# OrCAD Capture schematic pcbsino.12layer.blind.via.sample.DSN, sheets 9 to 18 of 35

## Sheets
9 Pg10: DDR3 VTT: size C
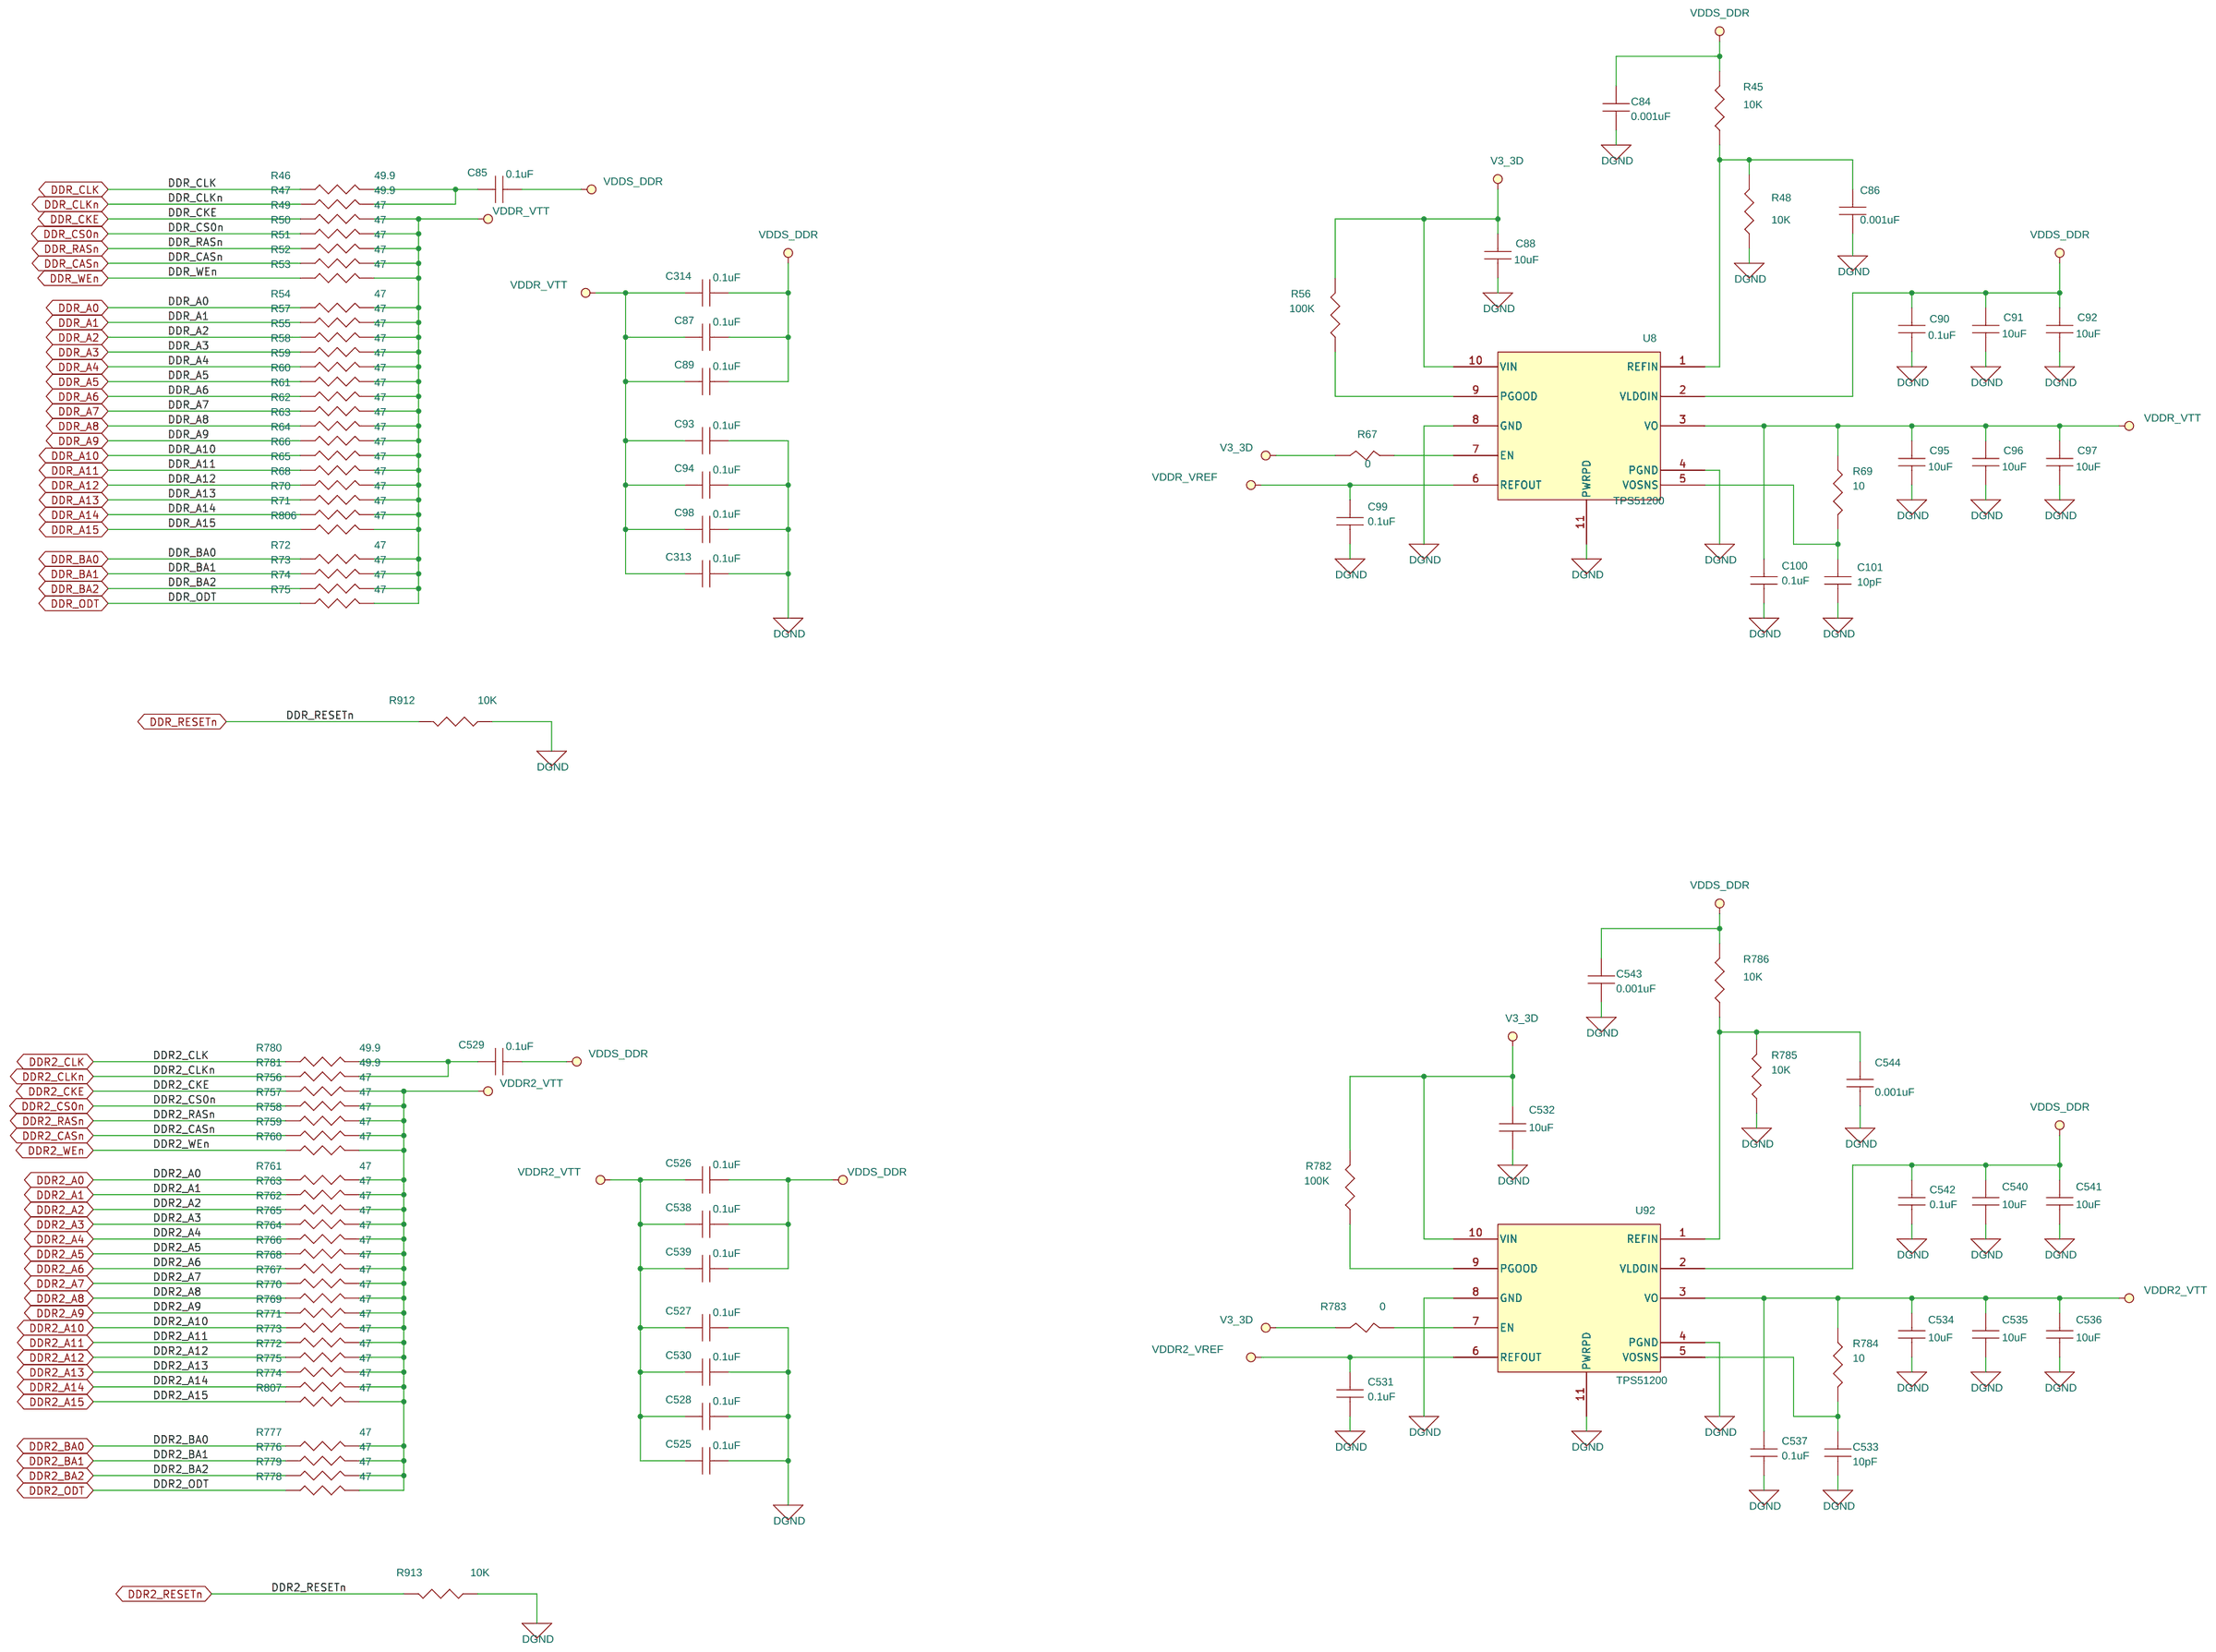
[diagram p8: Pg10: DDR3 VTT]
10 Pg01: Title Page
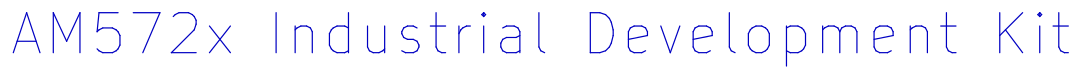
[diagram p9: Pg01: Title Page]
11 Pg34: IDK Mods: size B
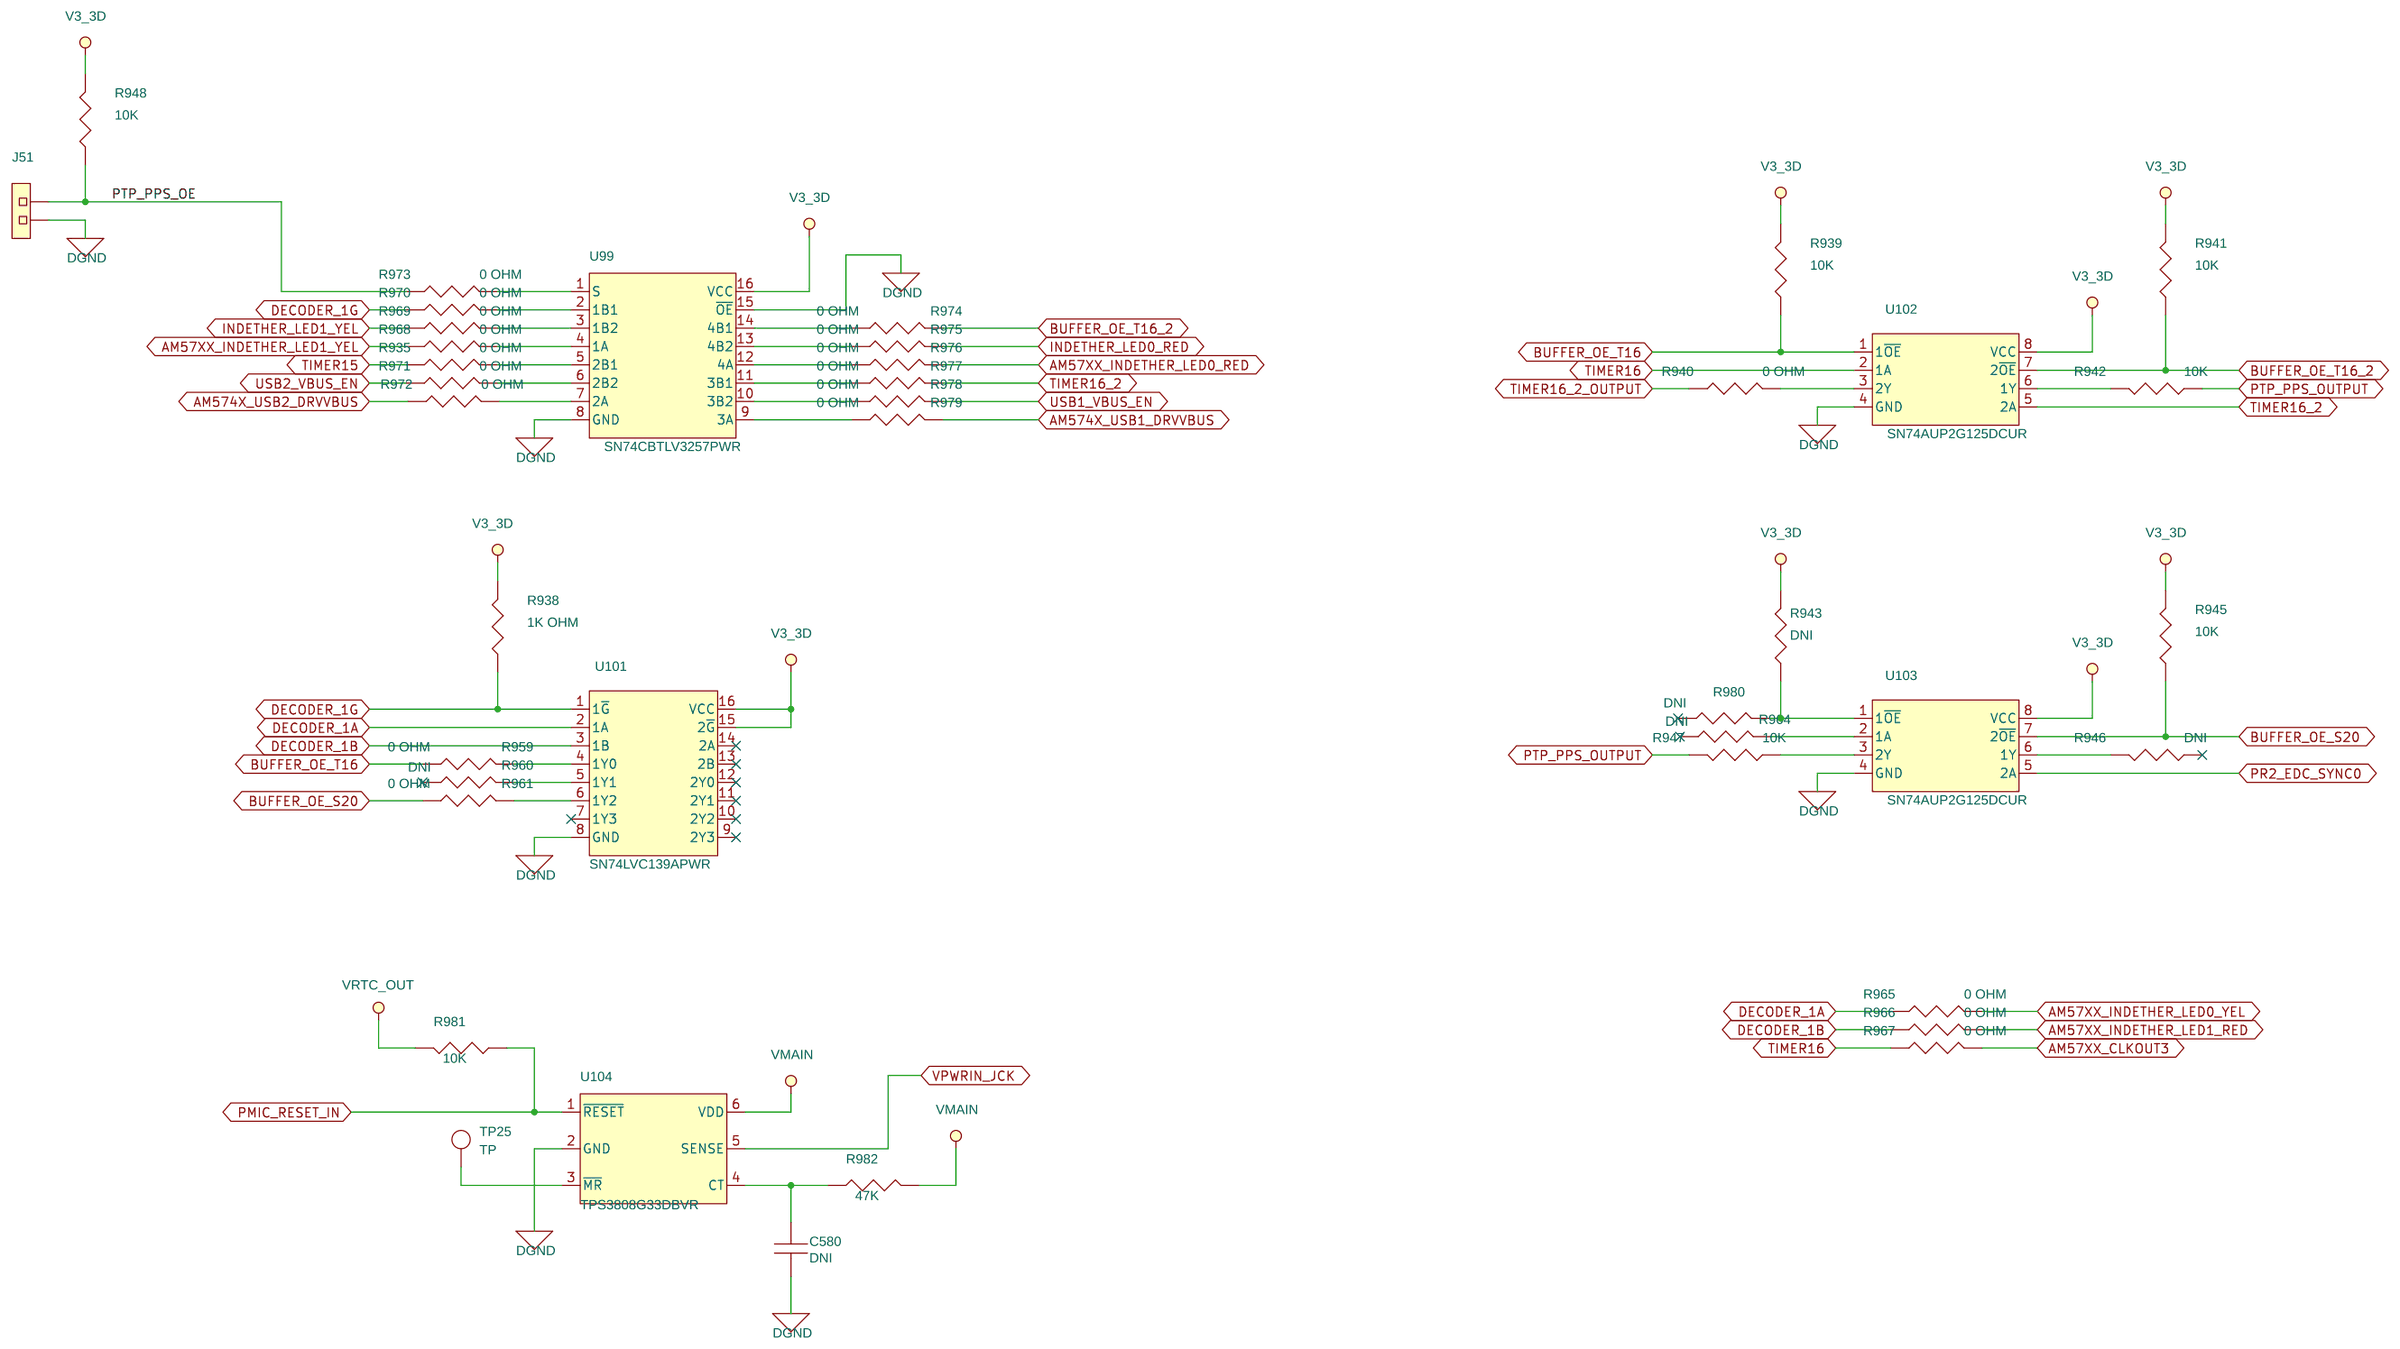
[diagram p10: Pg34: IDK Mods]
12 Pg29: Profibus: size C
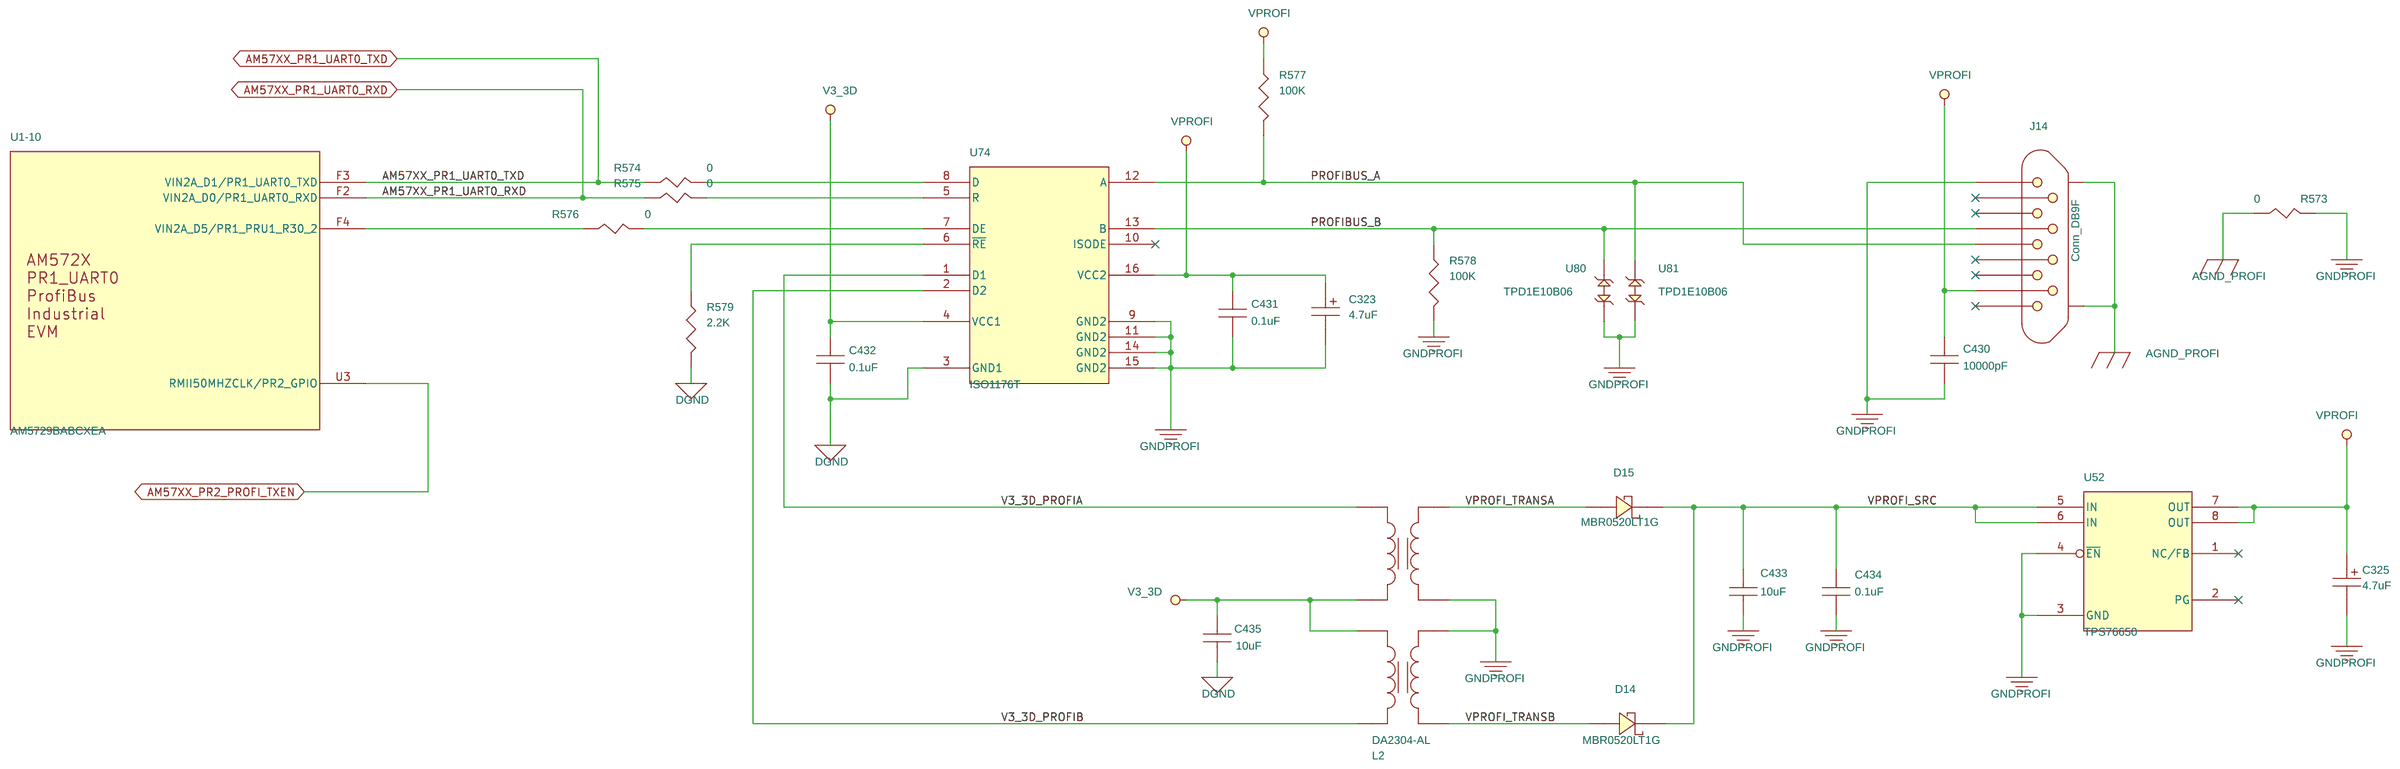
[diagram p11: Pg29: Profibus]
13 Pg16: Camera #1: size C
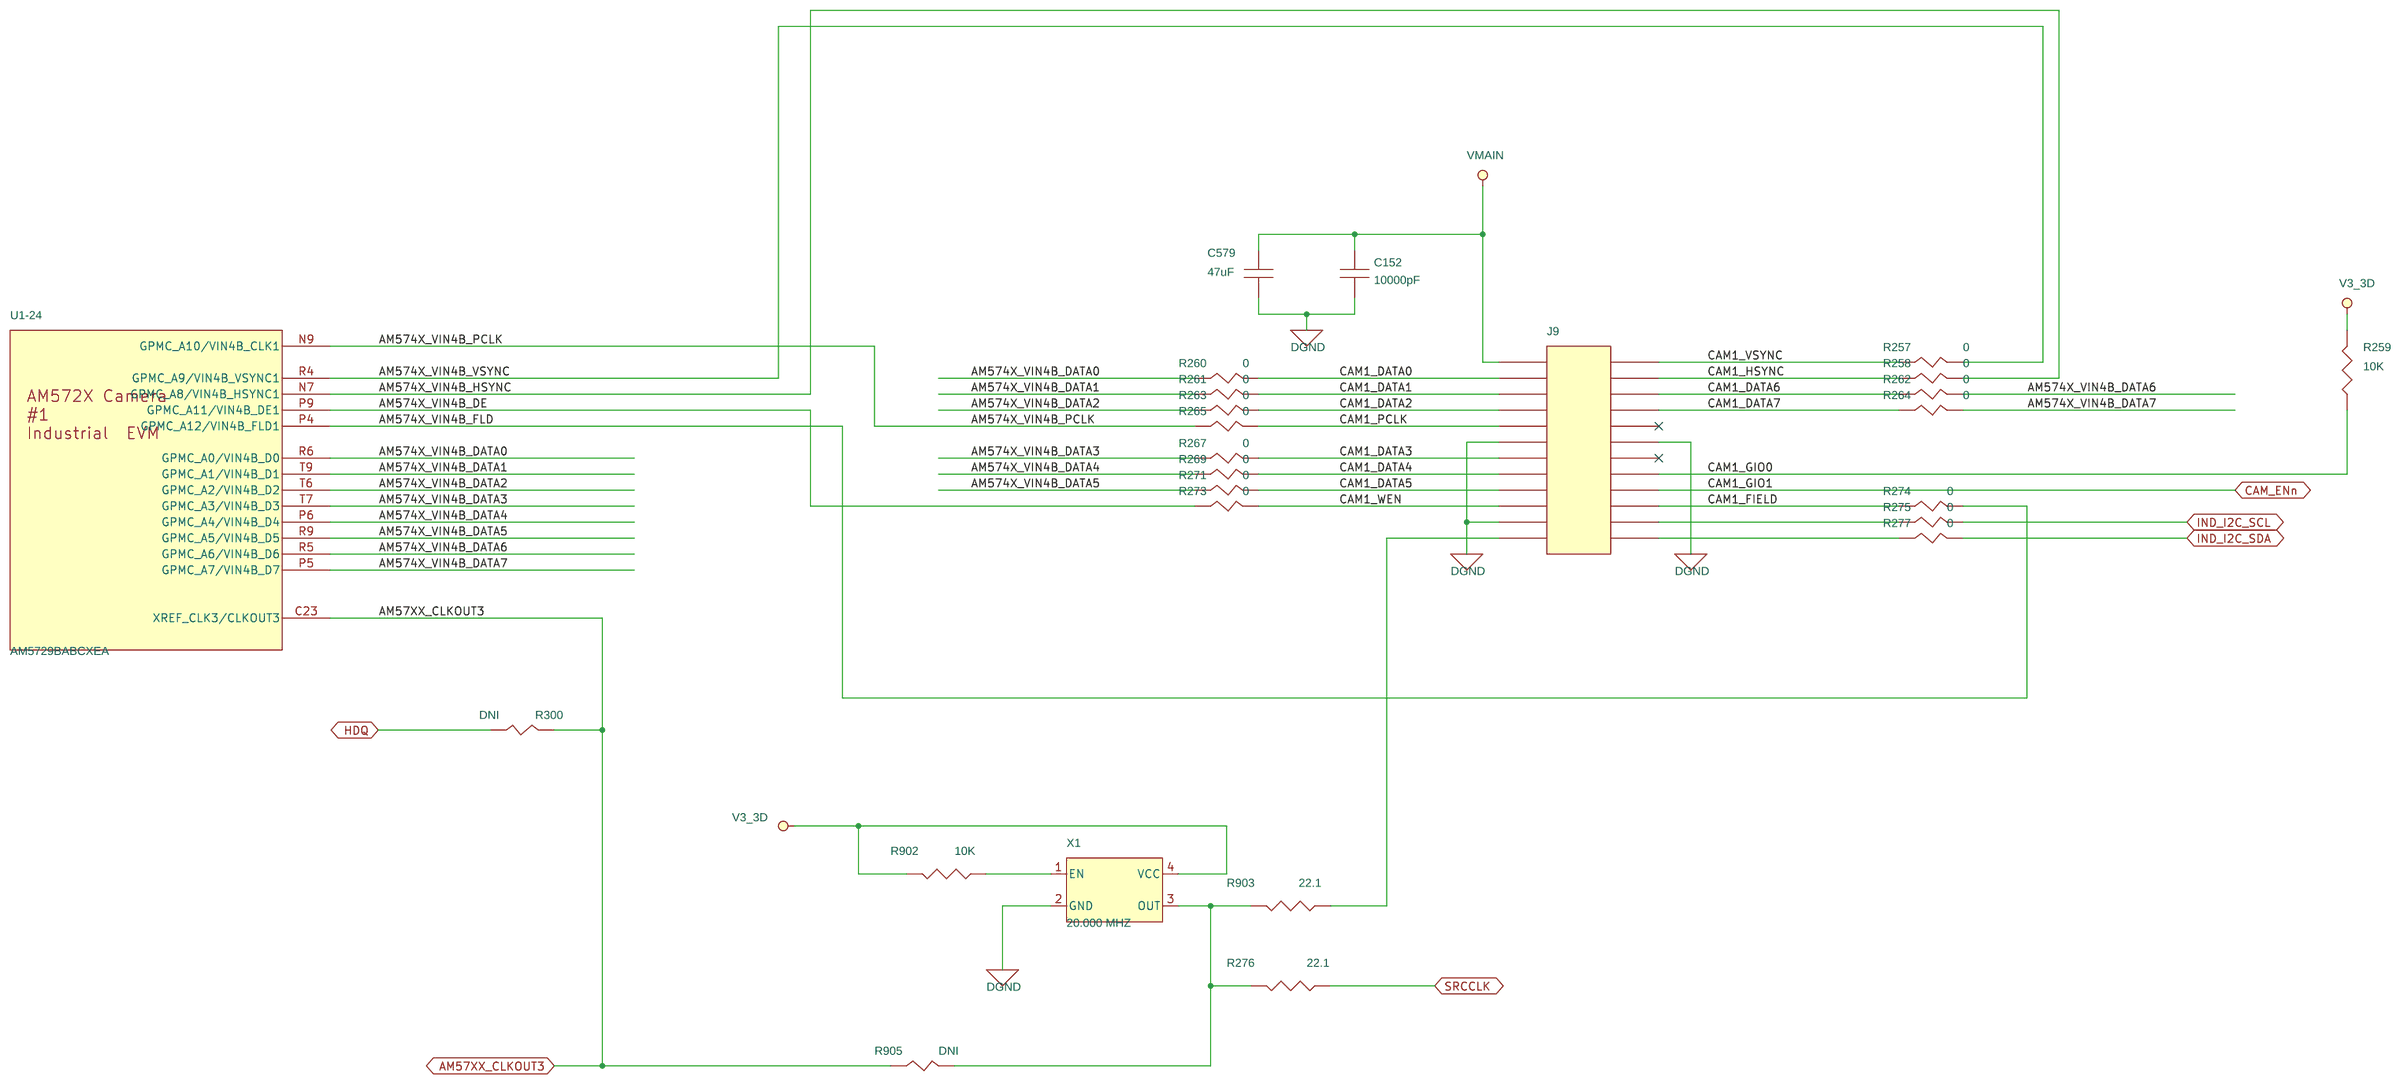
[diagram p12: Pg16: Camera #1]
14 Pg26: USB #1 3.0: size C
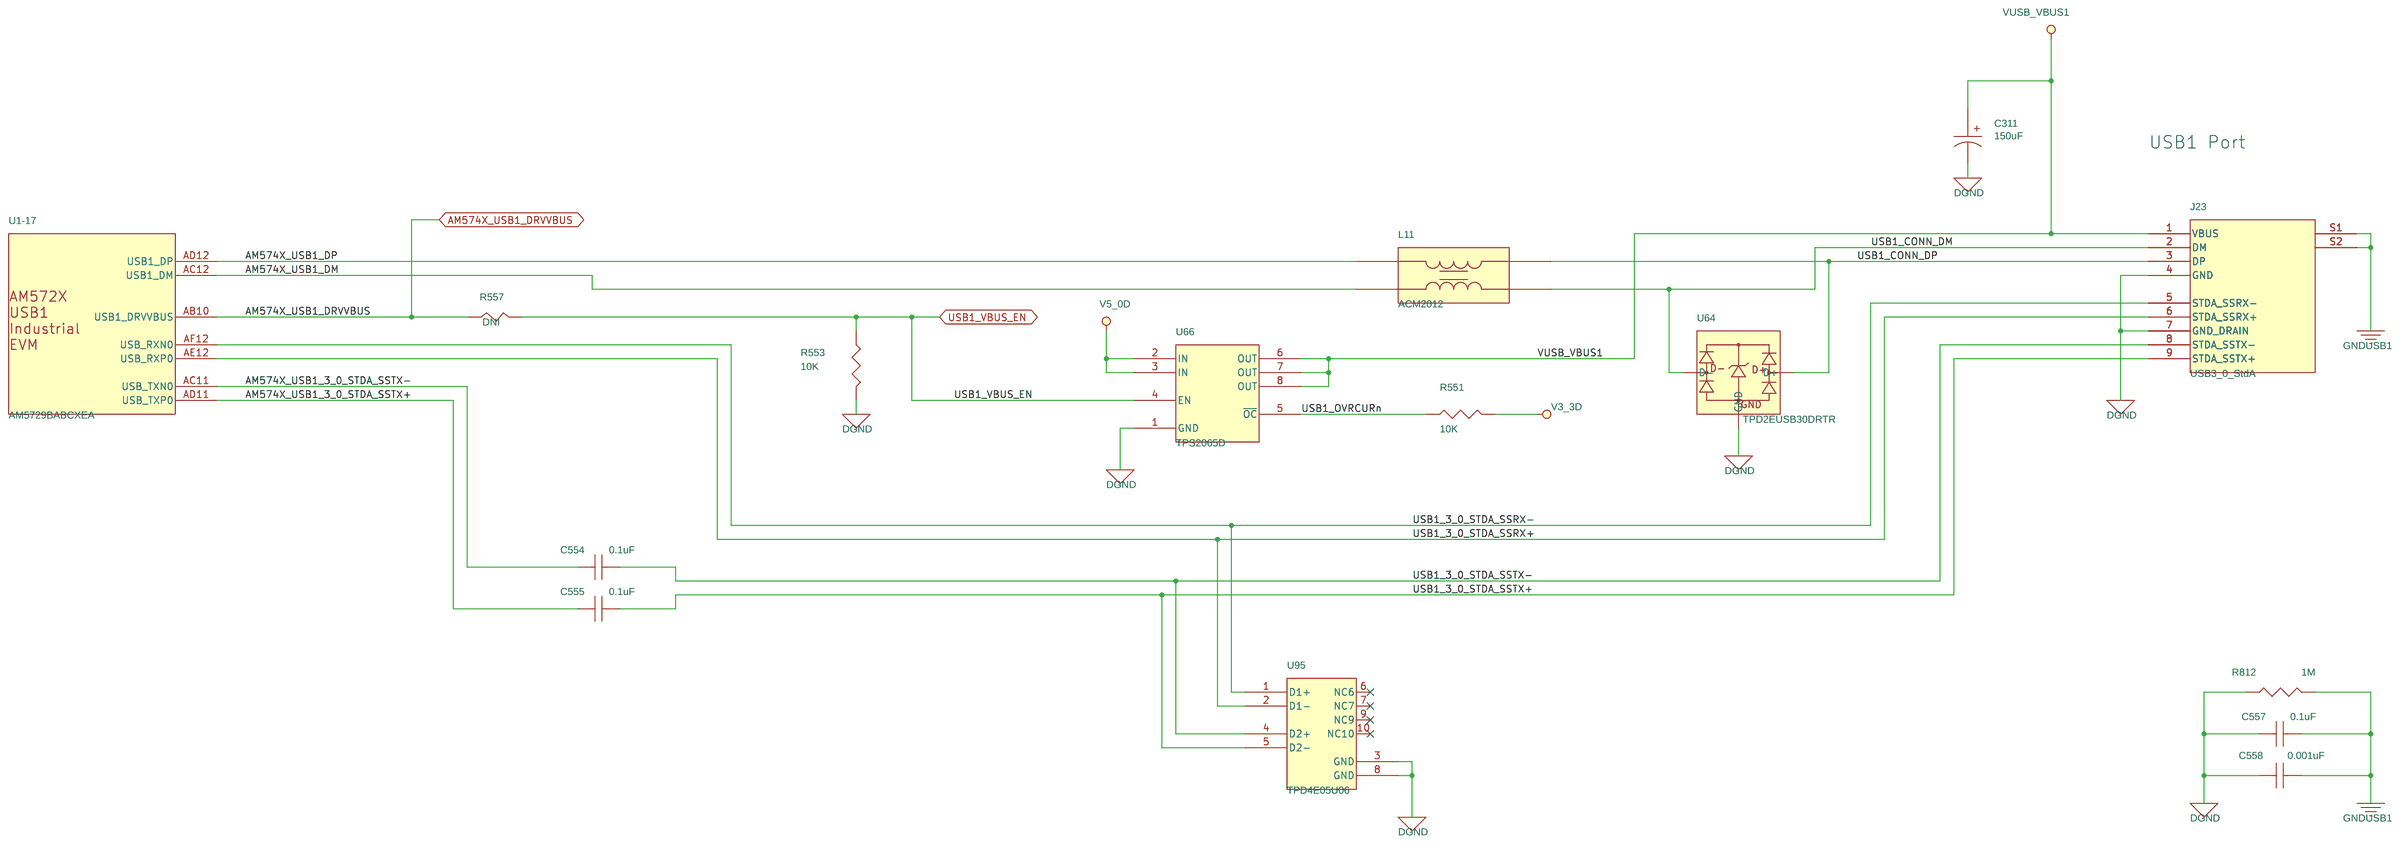
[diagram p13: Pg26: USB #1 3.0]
15 Pg23: JTAG Debug: size C
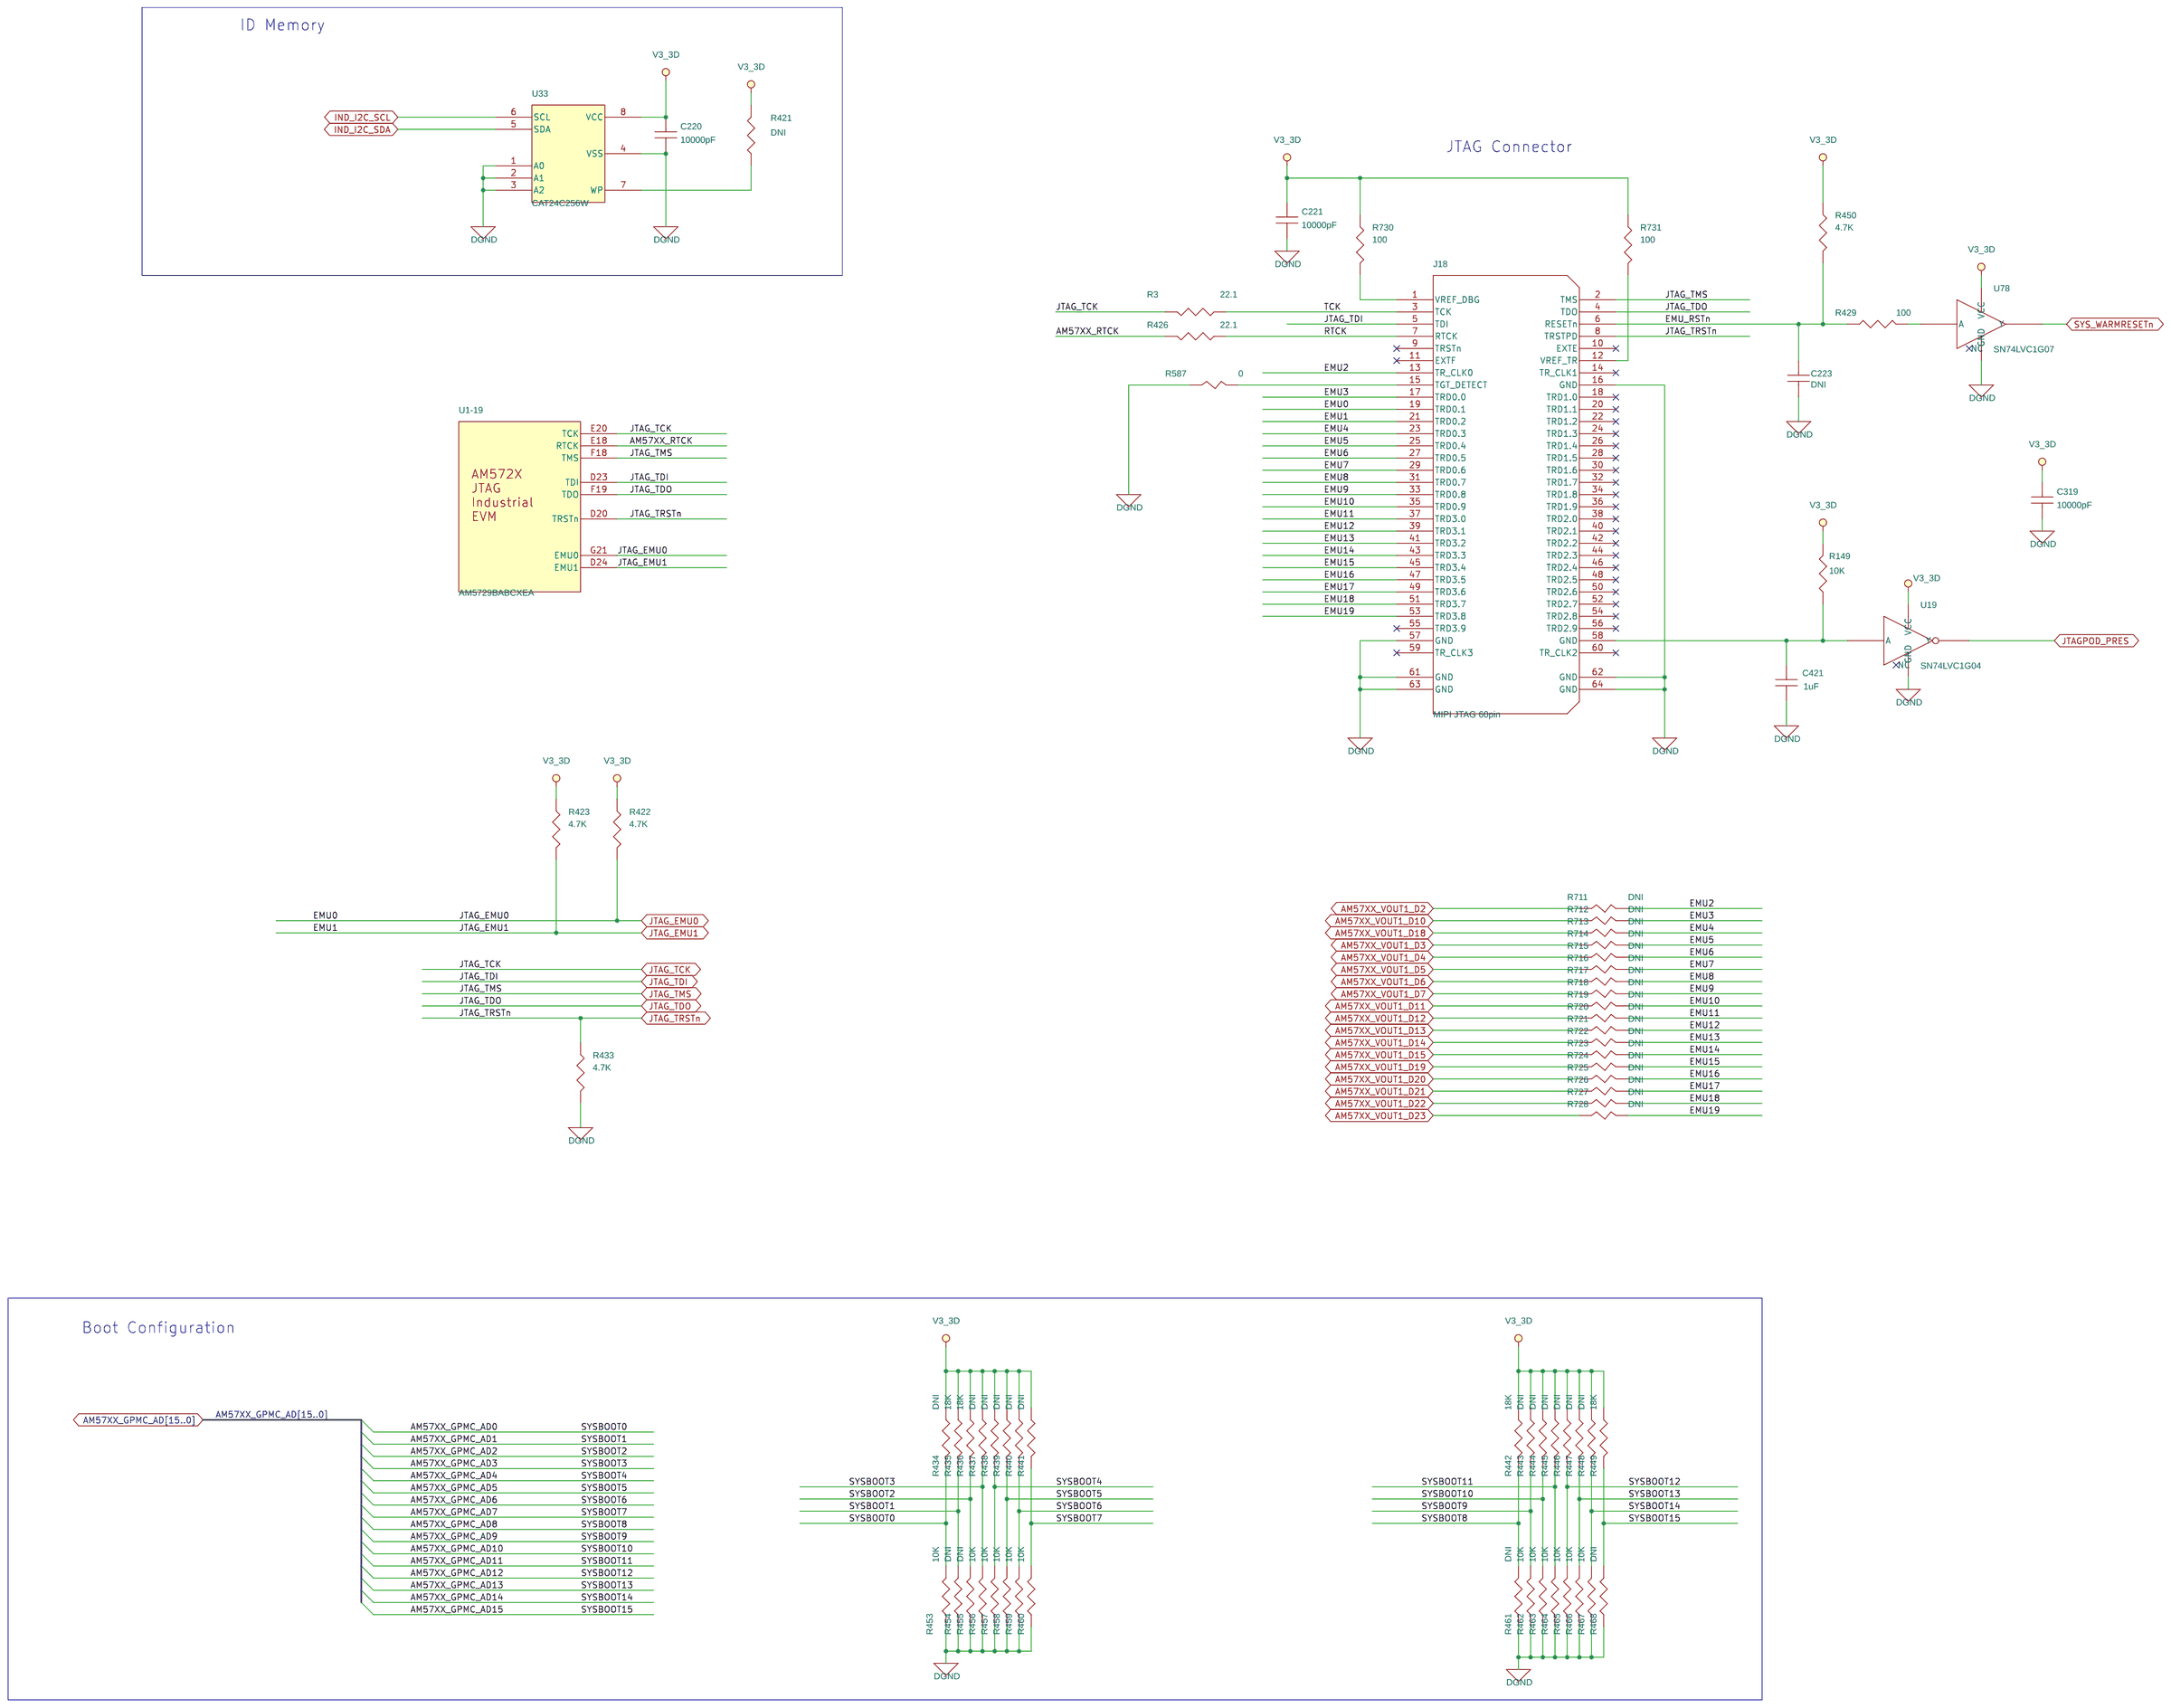
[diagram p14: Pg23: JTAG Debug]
16 Pg27: USB #2 2.0: size C
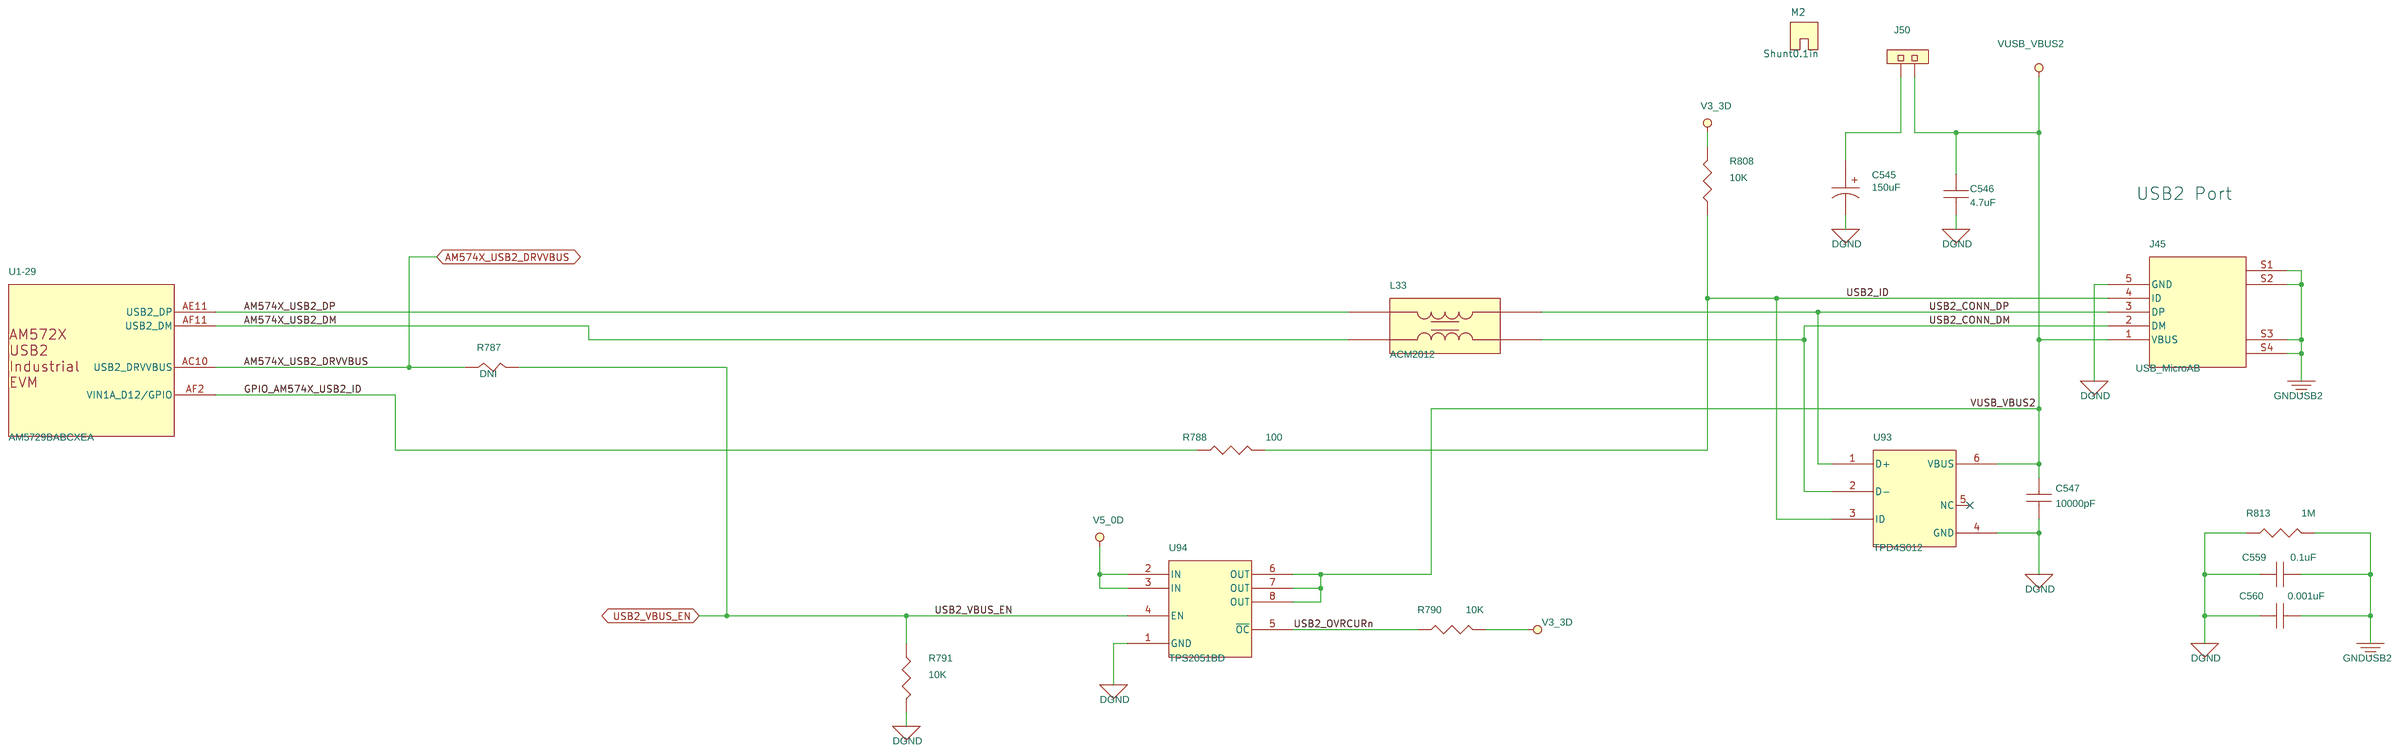
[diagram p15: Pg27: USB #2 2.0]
17 Pg12: ICSS1 Ethernet 1: size C
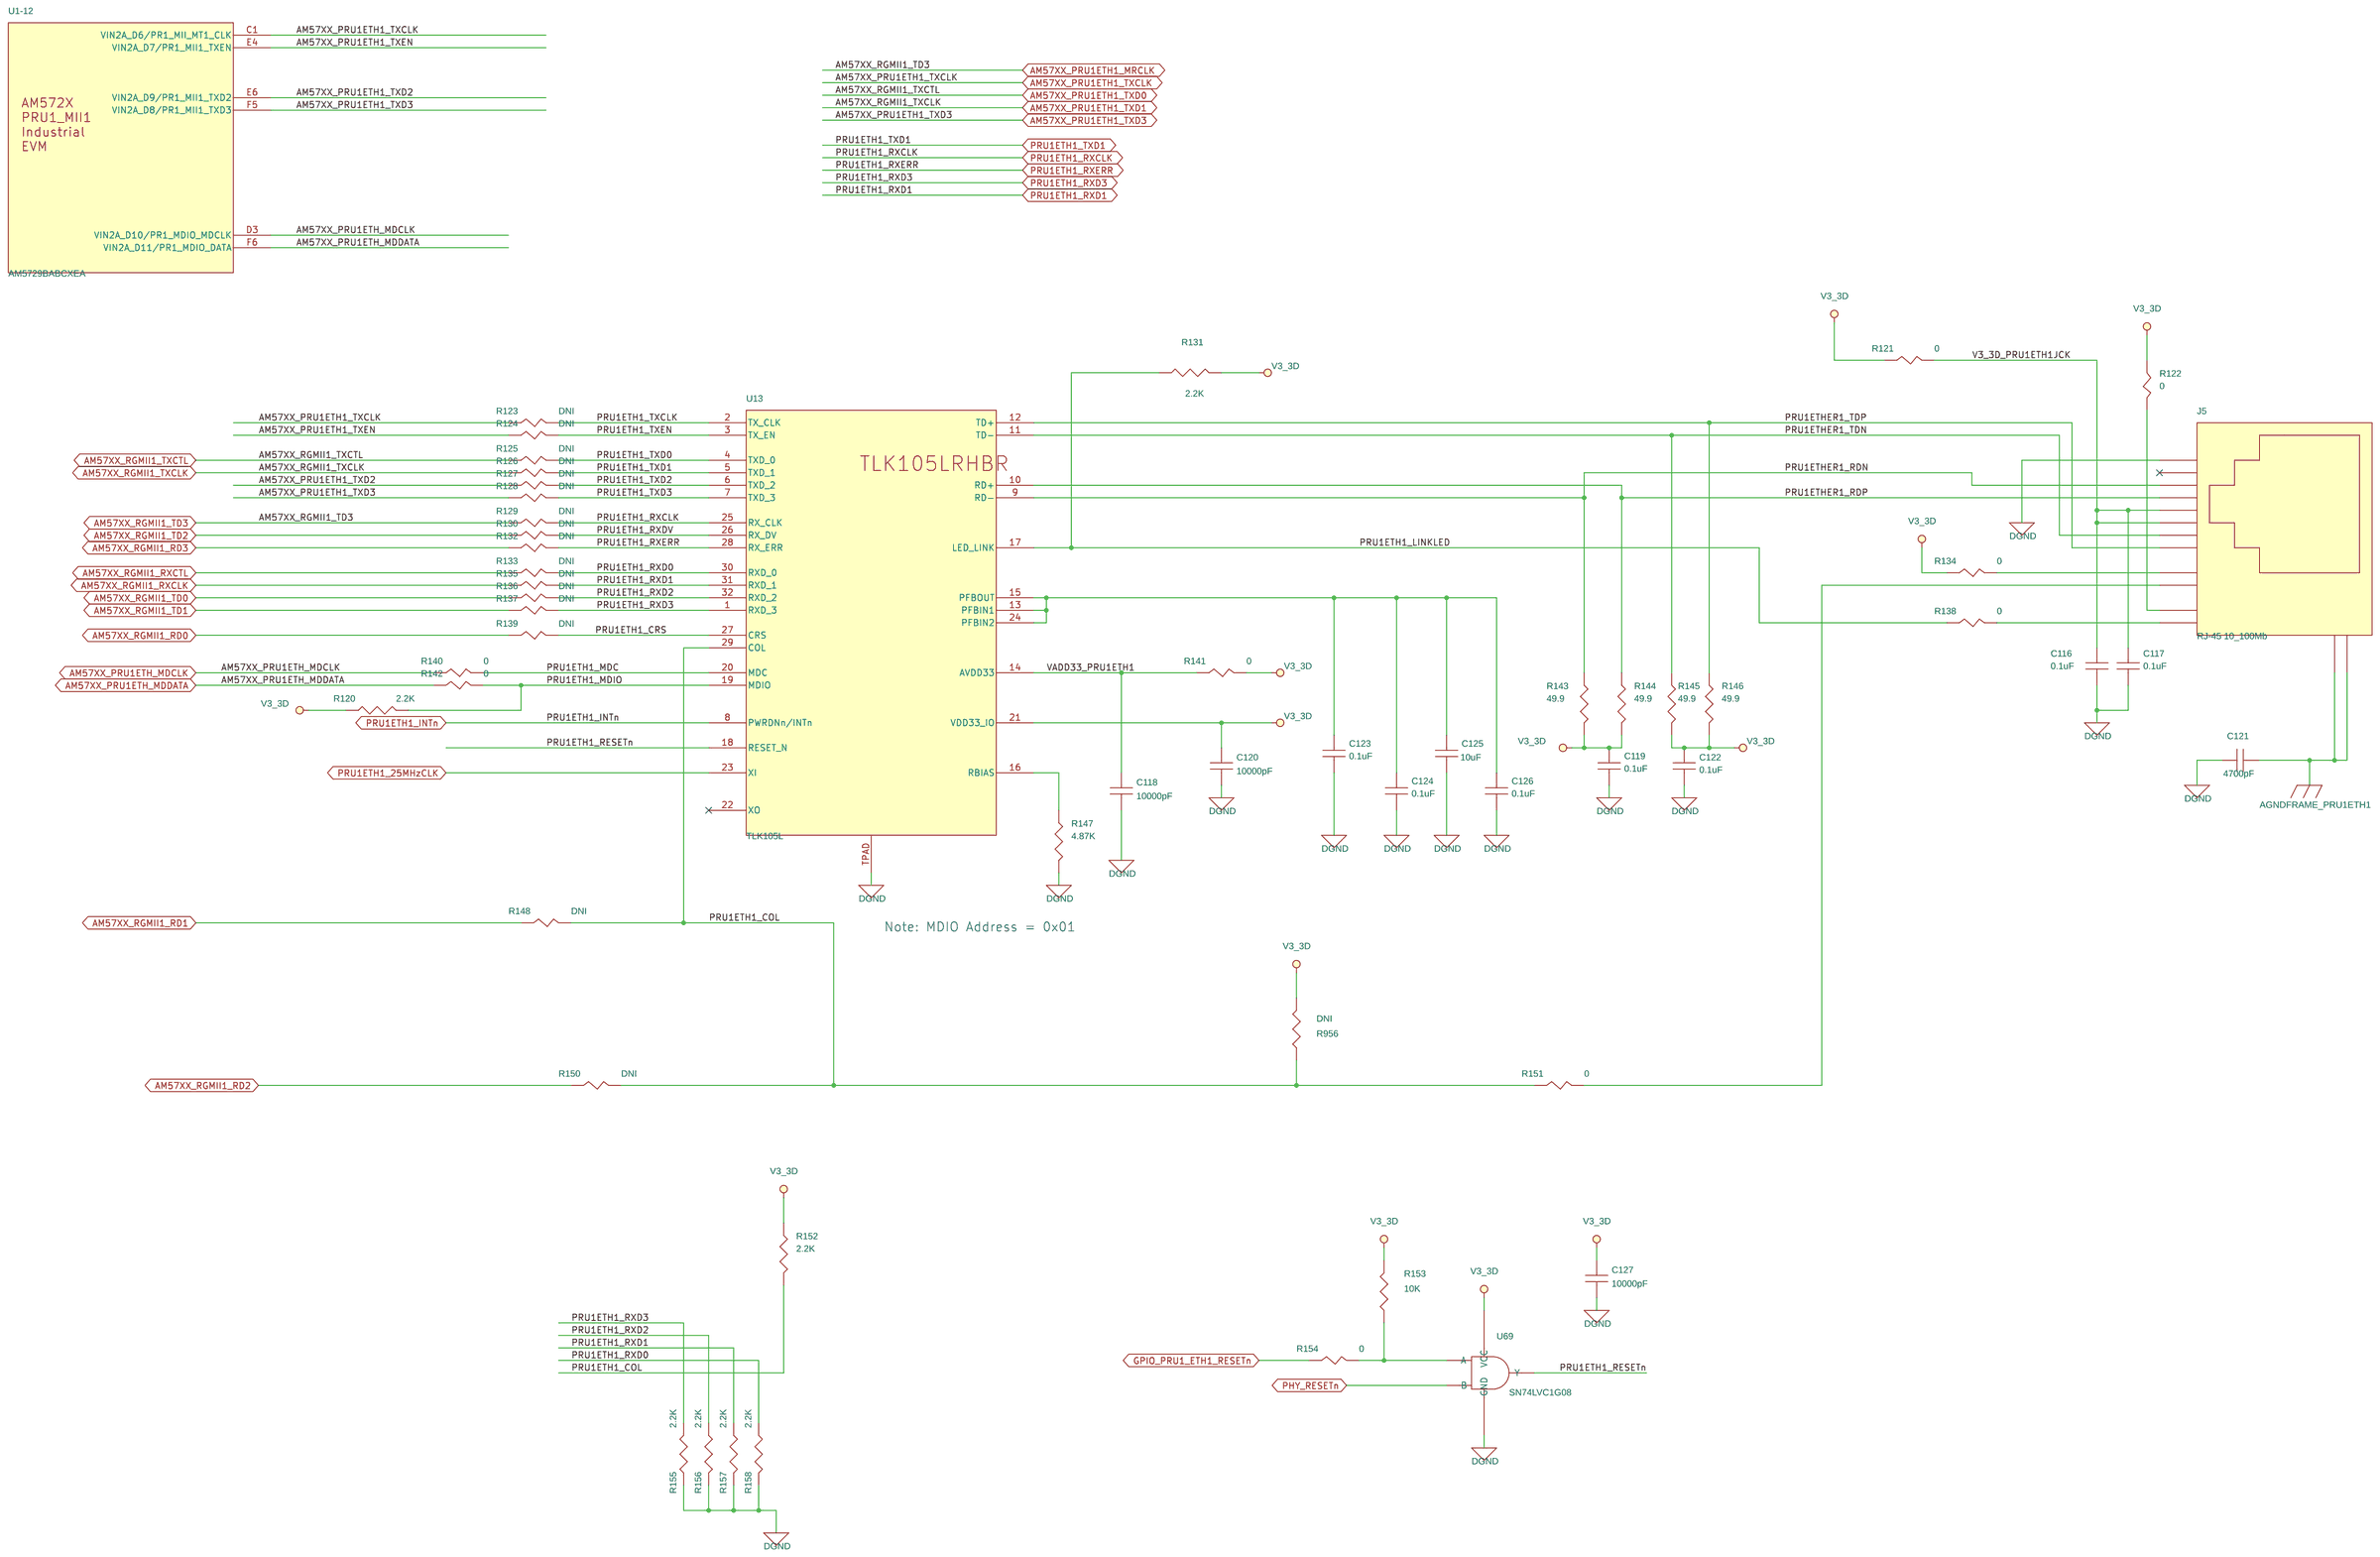
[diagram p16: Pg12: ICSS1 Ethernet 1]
18 Pg20: Industrial I/O: size C
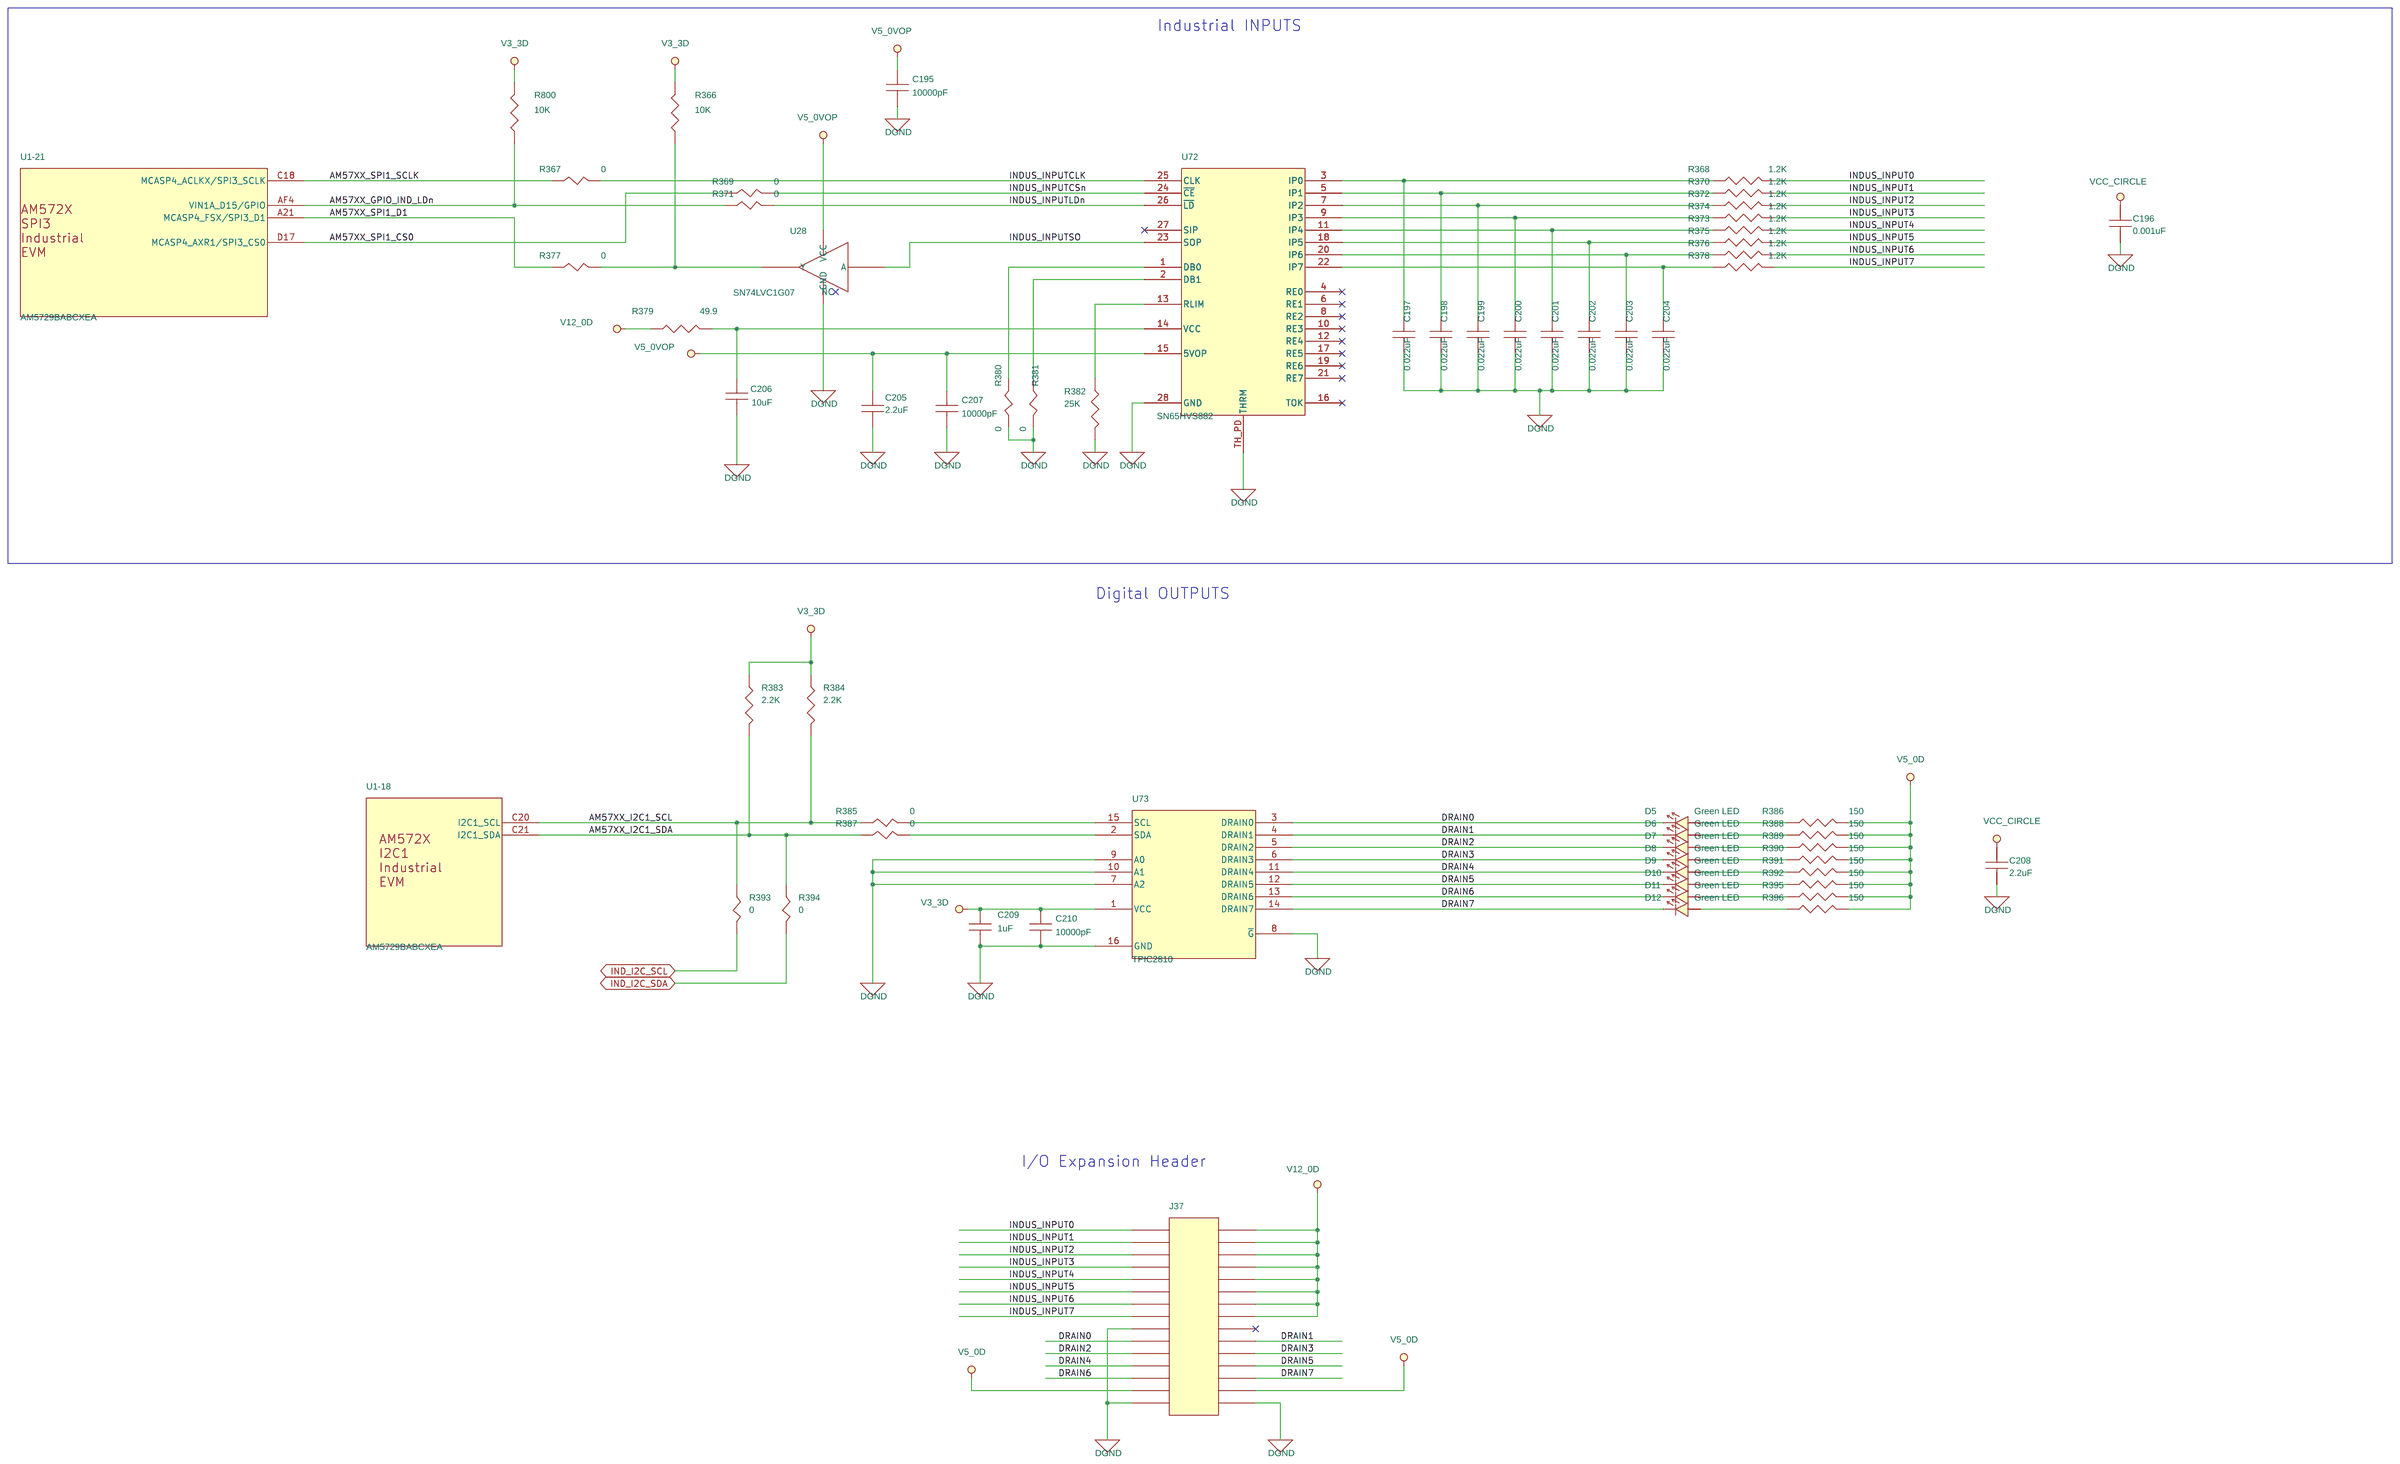
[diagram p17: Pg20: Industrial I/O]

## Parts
sheet Pg10: DDR3 VTT
C84  0.001uF  [SM-7351-CAP-0402]
C85  0.1uF  [CC0402]
C86  0.001uF  [SM-7351-CAP-0402]
C87  0.1uF  [CC0402]
C88  10uF  [CC0805]
C89  0.1uF  [CC0402]
C90  0.1uF  [CC0402]
C91  10uF  [CC0805]
C92  10uF  [CC0805]
C93  0.1uF  [CC0402]
C94  0.1uF  [CC0402]
C95  10uF  [CC0805]
C96  10uF  [CC0805]
C97  10uF  [CC0805]
C98  0.1uF  [CC0402]
C99  0.1uF  [CC0402]
C100  0.1uF  [CC0402]
C101  10pF  [SM-7351-CAP-0402]
C313  0.1uF  [CC0402]
C314  0.1uF  [CC0402]
C525  0.1uF  [CC0402]
C526  0.1uF  [CC0402]
C527  0.1uF  [CC0402]
C528  0.1uF  [CC0402]
C529  0.1uF  [CC0402]
C530  0.1uF  [CC0402]
C531  0.1uF  [CC0402]
C532  10uF  [CC0805]
C533  10pF  [SM-7351-CAP-0402]
C534  10uF  [CC0805]
C535  10uF  [CC0805]
C536  10uF  [CC0805]
C537  0.1uF  [CC0402]
C538  0.1uF  [CC0402]
C539  0.1uF  [CC0402]
C540  10uF  [CC0805]
C541  10uF  [CC0805]
C542  0.1uF  [CC0402]
C543  0.001uF  [SM-7351-CAP-0402]
C544  0.001uF  [SM-7351-CAP-0402]
R45  10K  [SM-7351-RES-0402]
R46  49.9  [SM-7351-RES-0402]
R47  49.9  [SM-7351-RES-0402]
R48  10K  [SM-7351-RES-0402]
R49  47  [SM-7351-RES-0402]
R50  47  [SM-7351-RES-0402]
R51  47  [SM-7351-RES-0402]
R52  47  [SM-7351-RES-0402]
R53  47  [SM-7351-RES-0402]
R54  47  [SM-7351-RES-0402]
R55  47  [SM-7351-RES-0402]
R56  100K  [SM-7351-RES-0402]
R57  47  [SM-7351-RES-0402]
R58  47  [SM-7351-RES-0402]
R59  47  [SM-7351-RES-0402]
R60  47  [SM-7351-RES-0402]
R61  47  [SM-7351-RES-0402]
R62  47  [SM-7351-RES-0402]
R63  47  [SM-7351-RES-0402]
R64  47  [SM-7351-RES-0402]
R65  47  [SM-7351-RES-0402]
R66  47  [SM-7351-RES-0402]
R67  0  [SM-7351-RES-0402]
R68  47  [SM-7351-RES-0402]
R69  10  [SM-7351-RES-0402]
R70  47  [SM-7351-RES-0402]
R71  47  [SM-7351-RES-0402]
R72  47  [SM-7351-RES-0402]
R73  47  [SM-7351-RES-0402]
R74  47  [SM-7351-RES-0402]
R75  47  [SM-7351-RES-0402]
R756  47  [SM-7351-RES-0402]
R757  47  [SM-7351-RES-0402]
R758  47  [SM-7351-RES-0402]
R759  47  [SM-7351-RES-0402]
R760  47  [SM-7351-RES-0402]
R761  47  [SM-7351-RES-0402]
R762  47  [SM-7351-RES-0402]
R763  47  [SM-7351-RES-0402]
R764  47  [SM-7351-RES-0402]
R765  47  [SM-7351-RES-0402]
R766  47  [SM-7351-RES-0402]
R767  47  [SM-7351-RES-0402]
R768  47  [SM-7351-RES-0402]
R769  47  [SM-7351-RES-0402]
R770  47  [SM-7351-RES-0402]
R771  47  [SM-7351-RES-0402]
R772  47  [SM-7351-RES-0402]
R773  47  [SM-7351-RES-0402]
R774  47  [SM-7351-RES-0402]
R775  47  [SM-7351-RES-0402]
R776  47  [SM-7351-RES-0402]
R777  47  [SM-7351-RES-0402]
R778  47  [SM-7351-RES-0402]
R779  47  [SM-7351-RES-0402]
R780  49.9  [SM-7351-RES-0402]
R781  49.9  [SM-7351-RES-0402]
R782  100K  [SM-7351-RES-0402]
R783  0  [SM-7351-RES-0402]
R784  10  [SM-7351-RES-0402]
R785  10K  [SM-7351-RES-0402]
R786  10K  [SM-7351-RES-0402]
R806  47  [SM-7351-RES-0402]
R807  47  [SM-7351-RES-0402]
R912  10K  [SM-7351-RES-0402]
R913  10K  [SM-7351-RES-0402]
U8  TPS51200  [drcpso_10pin]
U92  TPS51200  [drcpso_10pin]
sheet Pg12: ICSS1 Ethernet 1
C116  0.1uF  [CC0402]
C117  0.1uF  [CC0402]
C118  10000pF  [CC0402]
C119  0.1uF  [CC0402]
C120  10000pF  [CC0402]
C121  4700pF  [CC0402]
C122  0.1uF  [CC0402]
C123  0.1uF  [CC0402]
C124  0.1uF  [CC0402]
C125  10uF  [CC0805]
C126  0.1uF  [CC0402]
C127  10000pF  [CC0402]
J5  RJ-45 10_100Mb  [CNRJ45-1X1WLED]
R120  2.2K  [sm-7351-res-0402]
R121  0  [SM-7351-RES-0402]
R122  0  [SM-7351-RES-0402]
R123  DNI  [SM-7351-RES-0402]
R124  DNI  [SM-7351-RES-0402]
R125  DNI  [SM-7351-RES-0402]
R126  DNI  [SM-7351-RES-0402]
R127  DNI  [SM-7351-RES-0402]
R128  DNI  [SM-7351-RES-0402]
R129  DNI  [SM-7351-RES-0402]
R130  DNI  [SM-7351-RES-0402]
R131  2.2K  [sm-7351-res-0402]
R132  DNI  [SM-7351-RES-0402]
R133  DNI  [SM-7351-RES-0402]
R134  0  [SM-7351-RES-0402]
R135  DNI  [SM-7351-RES-0402]
R136  DNI  [SM-7351-RES-0402]
R137  DNI  [SM-7351-RES-0402]
R138  0  [SM-7351-RES-0603]
R139  DNI  [SM-7351-RES-0402]
R140  0  [SM-7351-RES-0402]
R141  0  [SM-7351-RES-0603]
R142  0  [SM-7351-RES-0402]
R143  49.9  [SM-7351-RES-0402]
R144  49.9  [SM-7351-RES-0402]
R145  49.9  [SM-7351-RES-0402]
R146  49.9  [SM-7351-RES-0402]
R147  4.87K  [SM-7351-RES-0402]
R148  DNI  [SM-7351-RES-0402]
R150  DNI  [SM-7351-RES-0402]
R151  0  [SM-7351-RES-0402]
R152  2.2K  [sm-7351-res-0402]
R153  10K  [SM-7351-RES-0402]
R154  0  [SM-7351-RES-0402]
R155  2.2K  [sm-7351-res-0402]
R156  2.2K  [sm-7351-res-0402]
R157  2.2K  [sm-7351-res-0402]
R158  2.2K  [sm-7351-res-0402]
R956  DNI  [sm-7351-res-0402]
U13  TLK105L  [qfn5x5-32-39m]
U69  SN74LVC1G08  [sm-so-sc70-5]
sheet Pg16: Camera #1
C152  10000pF  [CC0402]
C579  47uF  [CC1206]
J9  HEADER 12x2  [hdr2x12]
R257  0  [SM-7351-RES-0402]
R258  0  [SM-7351-RES-0402]
R259  10K  [SM-7351-RES-0402]
R260  0  [SM-7351-RES-0402]
R261  0  [SM-7351-RES-0402]
R262  0  [SM-7351-RES-0402]
R263  0  [SM-7351-RES-0402]
R264  0  [SM-7351-RES-0402]
R265  0  [SM-7351-RES-0402]
R267  0  [SM-7351-RES-0402]
R269  0  [SM-7351-RES-0402]
R271  0  [SM-7351-RES-0402]
R273  0  [SM-7351-RES-0402]
R274  0  [SM-7351-RES-0402]
R275  0  [SM-7351-RES-0402]
R276  22.1  [SM-7351-RES-0402]
R277  0  [SM-7351-RES-0402]
R300  DNI  [SM-7351-RES-0402]
R902  10K  [SM-7351-RES-0402]
R903  22.1  [SM-7351-RES-0402]
R905  DNI  [SM-7351-RES-0402]
X1  20.000 MHZ  [OSC7X5-71M]
sheet Pg20: Industrial I/O
C195  10000pF  [CC0402]
C196  0.001uF  [SM-7351-CAP-0402]
C197  0.022uF  [CC0402]
C198  0.022uF  [CC0402]
C199  0.022uF  [CC0402]
C200  0.022uF  [CC0402]
C201  0.022uF  [CC0402]
C202  0.022uF  [CC0402]
C203  0.022uF  [CC0402]
C204  0.022uF  [CC0402]
C205  2.2uF  [SM-7351-CAP-0805]
C206  10uF  [CC1206]
C207  10000pF  [CC0402]
C208  2.2uF  [SM-7351-CAP-0805]
C209  1uF  [CC0402]
C210  10000pF  [CC0402]
D5  Green LED  [sm_led_0805]
D6  Green LED  [sm_led_0805]
D7  Green LED  [sm_led_0805]
D8  Green LED  [sm_led_0805]
D9  Green LED  [sm_led_0805]
D10  Green LED  [sm_led_0805]
D11  Green LED  [sm_led_0805]
D12  Green LED  [sm_led_0805]
J37  Header 15x2 Female  [HDR2X15-344M]
R366  10K  [SM-7351-RES-0402]
R367  0  [SM-7351-RES-0402]
R368  1.2K  [SM-7351-CAP-0805]
R369  0  [SM-7351-RES-0402]
R370  1.2K  [SM-7351-CAP-0805]
R371  0  [SM-7351-RES-0402]
R372  1.2K  [SM-7351-CAP-0805]
R373  1.2K  [SM-7351-CAP-0805]
R374  1.2K  [SM-7351-CAP-0805]
R375  1.2K  [SM-7351-CAP-0805]
R376  1.2K  [SM-7351-CAP-0805]
R377  0  [SM-7351-RES-0402]
R378  1.2K  [SM-7351-CAP-0805]
R379  49.9  [SM-7351-CAP-0805]
R380  0  [SM-7351-RES-0402]
R381  0  [SM-7351-RES-0402]
R382  25K  [SM-7351-RES-0603]
R383  2.2K  [sm-7351-res-0402]
R384  2.2K  [sm-7351-res-0402]
R385  0  [SM-7351-RES-0402]
R386  150  [SM-7351-RES-0402]
R387  0  [SM-7351-RES-0402]
R388  150  [SM-7351-RES-0402]
R389  150  [SM-7351-RES-0402]
R390  150  [SM-7351-RES-0402]
R391  150  [SM-7351-RES-0402]
R392  150  [SM-7351-RES-0402]
R393  0  [SM-7351-RES-0402]
R394  0  [SM-7351-RES-0402]
R395  150  [SM-7351-RES-0402]
R396  150  [SM-7351-RES-0402]
R800  10K  [SM-7351-RES-0402]
U28  SN74LVC1G07  [u_5_dck]
U72  SN65HVS882  [u_28_pwp]
U73  TPIC2810  [u_16_d]
sheet Pg22: HDMI
U1  AM5729BABCXEA  [BGA23X23-760-117M]  (sections -1,-10,-11,-12,-13,-14,-15,-16,-17,-18,-19,-2,-20,-21,-22,-23,-24,-25,-26,-27,-28,-29,-3,-4,-5,-6,-7,-8,-9)
sheet Pg23: JTAG Debug
C220  10000pF  [CC0402]
C221  10000pF  [CC0402]
C223  DNI  [SM-7351-CAP-0402]
C319  10000pF  [CC0402]
C421  1uF  [CC0603]
J18  MIPI JTAG 60pin  [CNQSH030DA]
R3  22.1  [SM-7351-RES-0402]
R149  10K  [SM-7351-RES-0402]
R421  DNI  [SM-7351-RES-0402]
R422  4.7K  [SM-7351-RES-0402]
R423  4.7K  [SM-7351-RES-0402]
R426  22.1  [SM-7351-RES-0402]
R429  100  [SM-7351-RES-0402]
R433  4.7K  [SM-7351-RES-0402]
R434  DNI  [SM-7351-RES-0402]
R435  18K  [SM-7351-RES-0402]
R436  18K  [SM-7351-RES-0402]
R437  DNI  [SM-7351-RES-0402]
R438  DNI  [SM-7351-RES-0402]
R439  DNI  [SM-7351-RES-0402]
R440  DNI  [SM-7351-RES-0402]
R441  DNI  [SM-7351-RES-0402]
R442  18K  [SM-7351-RES-0402]
R443  DNI  [SM-7351-RES-0402]
R444  DNI  [SM-7351-RES-0402]
R445  DNI  [SM-7351-RES-0402]
R446  DNI  [SM-7351-RES-0402]
R447  DNI  [SM-7351-RES-0402]
R448  DNI  [SM-7351-RES-0402]
R449  18K  [SM-7351-RES-0402]
R450  4.7K  [SM-7351-RES-0402]
R453  10K  [SM-7351-RES-0402]
R454  DNI  [SM-7351-RES-0402]
R455  DNI  [SM-7351-RES-0402]
R456  10K  [SM-7351-RES-0402]
R457  10K  [SM-7351-RES-0402]
R458  10K  [SM-7351-RES-0402]
R459  10K  [SM-7351-RES-0402]
R460  10K  [SM-7351-RES-0402]
R461  DNI  [SM-7351-RES-0402]
R462  10K  [SM-7351-RES-0402]
R463  10K  [SM-7351-RES-0402]
R464  10K  [SM-7351-RES-0402]
R465  10K  [SM-7351-RES-0402]
R466  10K  [SM-7351-RES-0402]
R467  10K  [SM-7351-RES-0402]
R468  DNI  [SM-7351-RES-0402]
R587  0  [SM-7351-RES-0402]
R711  DNI  [SM-7351-RES-0402]
R712  DNI  [SM-7351-RES-0402]
R713  DNI  [SM-7351-RES-0402]
R714  DNI  [SM-7351-RES-0402]
R715  DNI  [SM-7351-RES-0402]
R716  DNI  [SM-7351-RES-0402]
R717  DNI  [SM-7351-RES-0402]
R718  DNI  [SM-7351-RES-0402]
R719  DNI  [SM-7351-RES-0402]
R720  DNI  [SM-7351-RES-0402]
R721  DNI  [SM-7351-RES-0402]
R722  DNI  [SM-7351-RES-0402]
R723  DNI  [SM-7351-RES-0402]
R724  DNI  [SM-7351-RES-0402]
R725  DNI  [SM-7351-RES-0402]
R726  DNI  [SM-7351-RES-0402]
R727  DNI  [SM-7351-RES-0402]
R728  DNI  [SM-7351-RES-0402]
R730  100  [SM-7351-RES-0402]
R731  100  [SM-7351-RES-0402]
U19  SN74LVC1G04  [SC70-5-43M]
U33  CAT24C256W  [SOIC_8]
U78  SN74LVC1G07  [SC70-5-43M]
sheet Pg26: USB #1 3.0
C311  150uF  [SM-7351-CAP-2917]
C554  0.1uF  [CC0402]
C555  0.1uF  [CC0402]
C557  0.1uF  [CC0402]
C558  0.001uF  [SM-7351-CAP-0402]
J23  USB3_0_StdA  [cn_lpaf3102nl]
L11  ACM2012  [ACM2012H]
R551  10K  [SM-7351-RES-0402]
R553  10K  [SM-7351-RES-0402]
R557  DNI  [SM-7351-RES-0402]
R812  1M  [SM-7351-RES-0402]
U64  TPD2EUSB30DRTR  [SOT1X1-3-20M]
U66  TPS2065D  [U_8_D]
U95  TPD4E05U06  [USON2X1-10-22M]
sheet Pg27: USB #2 2.0
C545  150uF  [SM-7351-CAP-2917]
C546  4.7uF  [SM-7351-CAP-0603]
C547  10000pF  [CC0402]
C559  0.1uF  [CC0402]
C560  0.001uF  [SM-7351-CAP-0402]
J45  USB_MicroAB  [ZX62-AB-5PA]
J50  HEADER 2  [header_2x1]
L33  ACM2012  [ACM2012H]
M2  Shunt0.1in  [none]
R787  DNI  [SM-7351-RES-0402]
R788  100  [SM-7351-RES-0402]
R790  10K  [SM-7351-RES-0402]
R791  10K  [SM-7351-RES-0402]
R808  10K  [SM-7351-RES-0402]
R813  1M  [SM-7351-RES-0402]
U93  TPD4S012  [U_6_DRY]
U94  TPS2051BD  [U_8_D]
sheet Pg29: Profibus
C323  4.7uF  [sm-7351-cap-0805]
C325  4.7uF  [sm-7351-cap-0805]
C430  10000pF  [CC0402]
C431  0.1uF  [CC0402]
C432  0.1uF  [CC0402]
C433  10uF  [CC0805]
C434  0.1uF  [CC0402]
C435  10uF  [CC1206]
D14  MBR0520LT1G  [DIO_SOD-123]
D15  MBR0520LT1G  [DIO_SOD-123]
J14  Conn_DB9F  [NorComp_db9F_SMD]
L2  DA2304-AL  [DA2304]
R573  0  [SM-7351-RES-0402]
R574  0  [SM-7351-RES-0402]
R575  0  [SM-7351-RES-0402]
R576  0  [SM-7351-RES-0402]
R577  100K  [SM-7351-RES-0402]
R578  100K  [SM-7351-RES-0402]
R579  2.2K  [sm-7351-res-0402]
U52  TPS76650  [soic_8]
U74  ISO1176T  [u_16_dw]
U80  TPD1E10B06  [tpd1e10b06-2l]
U81  TPD1E10B06  [tpd1e10b06-2l]
sheet Pg34: IDK Mods
C580  DNI  [SM-7351-CAP-0402]
J51  HEADER 2  [header_2x1]
R935  0 OHM  [RC0402]
R938  1K OHM  [RC0402]
R939  10K  [SM-7351-RES-0402]
R940  0 OHM  [RC0402]
R941  10K  [SM-7351-RES-0402]
R942  10K  [SM-7351-RES-0402]
R943  DNI  [SM-7351-RES-0402]
R945  10K  [SM-7351-RES-0402]
R946  DNI  [SM-7351-RES-0402]
R947  10K  [SM-7351-RES-0402]
R948  10K  [SM-7351-RES-0402]
R959  0 OHM  [RC0402]
R960  DNI  [RC0402]
R961  0 OHM  [RC0402]
R964  DNI  [RC0402]
R965  0 OHM  [RC0402]
R966  0 OHM  [RC0402]
R967  0 OHM  [RC0402]
R968  0 OHM  [RC0402]
R969  0 OHM  [RC0402]
R970  0 OHM  [RC0402]
R971  0 OHM  [RC0402]
R972  0 OHM  [RC0402]
R973  0 OHM  [RC0402]
R974  0 OHM  [RC0402]
R975  0 OHM  [RC0402]
R976  0 OHM  [RC0402]
R977  0 OHM  [RC0402]
R978  0 OHM  [RC0402]
R979  0 OHM  [RC0402]
R980  DNI  [RC0402]
R981  10K  [SM-7351-RES-0402]
R982  47K  [SM-7351-RES-0402]
TP25  TP  [TH_TP_5002]
U99  SN74CBTLV3257PWR  [sop65p640x120-16n]
U101  SN74LVC139APWR  [SOP65P640X120-16N]
U102  SN74AUP2G125DCUR  [SOP50P310X90-8]
U103  SN74AUP2G125DCUR  [SOP50P310X90-8]
U104  TPS3808G33DBVR  [SOT-23-6]

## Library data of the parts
C84 C86 C196 C543 C544 C558 C560 = 1C_0.001uFCapacitor50V5%0402: Capacitor 0.001uF 50V 5% 0402; MANUFACTURER: AVX
C85 C87 C89 C90 C93 C94 C98-C100 C116 C117 C119 C122-C124 C126 C313 C314 C525-C531 C537-C539 C542 C554 C555 C557 C559 = CC0402JRX7R7BB104
C88 C91 C92 C95-C97 C125 C433 C532 C534-C536 C540 C541 = CL21A106KOQNNNG
C101 C533 = 1C_10pFCapacitor50V1%smd0402: Capacitor 10pF 50V 1% Ceramic 0402; MANUFACTURER: AVX
R45 R48 R149 R153 R259 R366 R421 R453-R468 R551 R553 R785 R786 R790 R791 R800 R808 R902 R912 R913 R939 R941-R943 R945-R948 R981 = RMCF0402FT10K0
R46 R47 R143-R146 R780 R781 = 1R_49.9OhmResistor1_16W0402: Resistor 49.9ohm 1/16W 1% 0402; MANUFACTURER: PANASONIC
R49-R55 R57-R66 R68 R70-R75 R756-R779 R806 R807 = 1R_47ohm1_16W1%smd0402: Resistor 47ohm 1/16W 1% 0402; MANUFACTURER: STACKPOLE ELECTRONICS
R56 R577 R578 R782 = 1R_100KOhmResistor1_16W0402: Resistor 100Kohm 1/16W 1% 0402; MANUFACTURER: STACKPOLE ELECTRONICS
R67 R121-R130 R132-R137 R139 R140 R142 R148 R150 R151 R154 R257 R258 R260-R265 R267 R269 R271 R273-R275 R277 R300 R367 R369 R371 R377 R380 R381 R385 R387 R393 R394 R557 R573-R576 R587 R711-R728 R783 R787 R905 = 1R_ZeroOhmResistor1_16W0402: Resistor Zero ohm Jumper 0402; MANUFACTURER: PANASONIC
R69 R784 = 1R_10ohm1_16W5%smd0402: Resistor 10ohm 1/16W 5% 0402; MANUFACTURER: STACKPOLE ELECTRONICS
U8 U92 = TPS51200DRCT: MANUFACTURER: TEXAS INSTRUMETNS
C118 C120 C127 C152 C195 C207 C210 C220 C221 C319 C430 C547 = CC0402KRX7R7BB103
C121 = 04025C472KAT2A
J5 = 2J_ConnectorRJ45_10_0: Connector MagRJ-45 Jack w/LED 10_100Mb - Auto MDIX; MANUFACTURER: Link
R120 R131 R152 R155-R158 R383 R384 R579 R956 = 1R_2.2KOhmResistor1_16W0402: MANUFACTURER: VishayDale
R138 R141 = 1R_ZeroOhmResistor1_16W0603: Resistor Zero ohm Jumper 0603; MANUFACTURER: PANASONIC
R147 = 1R_4.87Kohm1_16W1%smd0402: Resistor 4.87Kohm 1/16W 1% 0402; MANUFACTURER: STACKPOLE ELECTRONICS
U13 = TLK105LRHBR: MANUFACTURER: TEXAS INSTRUMENTS
U69 = SN74LVC1G08DCKR: MANUFACTURER: TI
C579 = CL31A476MPHNNNE
J9 = 2H_Header12x2: Dual Line Header 12x2pin Tin; MANUFACTURER: Sullins
R3 R276 R426 R903 = RMCF0402FT22R1
X1 = CB3LV-3C-20M0000
C197-C204 = C0402C223K5RACAUTO
C205 C208 = 1C_2.2uF16V10%SMD0805: Capacitor 2.2uF 16V 10% 0805; MANUFACTURER: Kemet
C206 C435 = GRT31CR61H106KE01L
C209 = CGB2A1X5R1E105K033BC
D5-D12 = 5988170107F: LED Green SMD 20mA 2V 0805; MANUFACTURER: Dialight
J37 = 2H_Header15x2_0.1in_Female: Header 15x2 0.1in pitch female throughhole; MANUFACTURER: FCI
R368 R370 R372-R376 R378 = ERJ-6ENF1201V
R379 = ERJ-6ENF49R9V
R382 = 1R_25Kohm1_10W0.1%smd0603: Resistor 25Kohm 1/10W 0.1% 0603; MANUFACTURER: Vishay
R386 R388-R392 R395 R396 = 1R_150ohm1_16W1%SMD0402: Resistor 150ohm 1/16W 5% 0402; MANUFACTURER: STACKPOLE ELECTRONICS
U28 U78 = SN74LVC1G07DCKRE4: MANUFACTURER: TEXAS INSTRUMENT
U72 = 1A_SN65HVS882: MANUFACTURER: TI
U73 = 1A_TPIC2810: MANUFACTURER: TI; MfrNum: TPIC2810D
U1 = AM5729BABCXEA
C223 C580 = C0402C104J4RACTU
C421 = CL10A105KB8NNNC
J18 = 2C_Conn_JTAGMIPI_60pin: JTAG MIPI Connector QSH 60 pins; MANUFACTURER: Samtec
R422 R423 R433 R450 = 1R_4.7KOhmResistor1_16W0402: Resistor 4.7Kohm 1/16W 5% 0402; MANUFACTURER: STACKPOLE ELECTRONICS
R429 R788 = 1R_100ohm1_16W1%SMD0402: Resistor 100ohm 1/10W 1% 0402; Cost100: 0.02; MANUFACTURER: PANASONIC; MfrNum: ERJ-2RKF1000X; PartName: 100ohm1/10W1%0402; TIIntPartnumber: 1R0246
R434-R449 = 1R_18KohmResistor1_10W1%smd0402: Resistor 18Kohm 1/10W 1% 0402; MANUFACTURER: PANASONIC
R730 R731 = 1R_100ohm1_10W1%SMD0402: Resistor 100ohm 1/10W 1% 0402; MANUFACTURER: PANASONIC; PartName: 100ohm1/10W1%0402
U19 = SN74LVC1G04DCKRE4: MANUFACTURER: TEXAS INSTRUMENTS
U33 = 1A_CAT24C256W: EEPROM 256Kb I2C SOIC8; MANUFACTURER: On Semiconductor
C311 C545 = T495D157K010ATE100
J23 = 1932258-1: Connector USB 3.0 Standard A RA; MANUFACTURER: TE CONNECTIVITY
L11 = ACM2012H-900-2P-T05: Power Transformer 45uH RS-485; MANUFACTURER: TDK
R812 R813 = 1R_1MOhmResistor1_16W0402: Resistor 1Mohm 1/16W 1% 0402; MANUFACTURER: STACKPOLE ELECTRONICS
U64 = TPD2EUSB30DRTR
U66 = 1A_TPS2065D: Power Distribution Switch Current Limited; MANUFACTURER: TI
U95 = TPD4E05U06DQAR: MANUFACTURER: TI
C546 = 1C_4.7uFCapacitor16V10%0603: Capacitor Ceramic 4.7uF 16V 10% 0603; MANUFACTURER: Taiyo Yuden
J45 = USB: MANUFACTURER: Hirose
J50 J51 = 2H_Header_0: Single Line Header 2pin Tin 0.1in pitch; MANUFACTURER: OnShoreTechnology
L33 = ACM2012H-900-2P-T05: Common Mode Filter for USB/HDMI; MANUFACTURER: TDK
M2 = 2H_Shunt0.1in: Shunt 0.1in pitch; MANUFACTURER: TE Connectivity
U93 = TPD4S012DRYR: MANUFACTURER: TI
U94 = 1A_TPS2051BD: Power Distribution Switch Current Limited 500mA; MANUFACTURER: TI
C323 C325 = 4.7uFCapacitor16V20%Tant: Capacitor 4.7uF 16V 20% Tantalum Low ESR; MANUFACTURER: Nichicon
C431 C432 C434 = CGA2B3X7R1H104K050BE
D14 D15 = MBR0520LT1G
J14 = 2C_Conn_DSUB9F: Connector DB9 Female RA SMD; MANUFACTURER: Norcomp
L2 = DA2304-ALB: MANUFACTURER: Coilcraft
U52 = TPS76650: MANUFACTURER: TI
U74 = 1A_ISO1176T: Isolated Profibus RS-485 Transceiver; MANUFACTURER: TI
U80 U81 = TPD1E10B06DPYR: TVS DIODE 5.5V 14V 2X1SON; MANUFACTURER: TI
R935 R940 R959-R961 R964-R980 = ERJ-2GE0R00X
R938 = ERJ-2GEJ102X
R982 = 1R_47KOhmResistor1_16W0402: Resistor 47Kohm 1/16W 1% 0402; MANUFACTURER: Vishay
TP25 = 2H_TestPointThroughHole: Testpoint Miniature Through Hole; DNI: DNI; MANUFACTURER: Keystone Electronics
U99 = SN74CBTLV3257PWR
U101 = SN74LVC139APWR
U102 U103 = SN74AUP2G125DCUR
U104 = TPS3808G33DBVR

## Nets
AGND_PROFI: J14.10 J14.11 R573.2(P2)
AGNDFRAME_PRU1ETH1: C121.2 J5.SHLD1 J5.SHLD2
DGND: C84.2 C86.2 C88.2 C90.2 C91.2 C92.2 C93.2 C94.2 C95.2 C96.2 C97.2 C98.2 C99.2 C100.2 C101.2 C116.2 C117.2 C118.2 C119.2 C120.2 C121.1 C122.2 C123.2 C124.2 C125.2 C126.2 C127.2 C152.2 C195.2 C196.2 C197.2 C198.2 C199.2 C200.2 C201.2 C202.2 C203.2 C204.2 C205.2 C206.2 C207.2 C208.2 C209.2 C210.2 C220.2 C221.2 C223.2 C311.2 C313.2 C319.2 C421.2 C432.2 C435.2 C525.2 C527.2 C528.2 C530.2 C531.2 C532.2 C533.2 C534.2 C535.2 C536.2 C537.2 C540.2 C541.2 C542.2 C543.2 C544.2 C545.2 C546.2 C547.2 C557.1 C558.1 C559.1 C560.1 C579.2 C580.2 J5.8 J9.11 J9.12 J9.21 J18.16(GND) J18.57(GND) J18.61(GND) J18.62(GND) J18.63(GND) J18.64(GND) J23.4(GND) J23.7(GND_DRAIN) J37.17 J37.29 J37.30 J45.5(GND) J51.2 R48.1 R147.1(P1) R155.1(P1) R156.1(P1) R157.1(P1) R158.1(P1) R380.1(P1) R381.1(P1) R382.1(P1) R433.1(P1) R453.1 R454.1 R455.1 R456.1 R457.1 R458.1 R459.1 R460.1 R461.1 R462.1 R463.1 R464.1 R465.1 R466.1 R467.1 R468.1 R553.2 R579.1(P1) R587.2(P2) R785.1 R791.2 R812.2(P2) R813.2(P2) R912.1 R913.1 U8.4(PGND) U8.8(GND) U8.11(PWRPD) U13.TPAD U19.3(GND) U28.3(GND) U33.1(A0) U33.2(A1) U33.3(A2) U33.4(VSS) U64.3(GND) U66.1(GND) U69.3(GND) U72.28(GND) U72.TH_PD(THRM) U73.7(A2) U73.8(~{G}) U73.9(A0) U73.10(A1) U73.16(GND) U74.3(GND1) U78.3(GND) U92.4(PGND) U92.8(GND) U92.11(PWRPD) U93.4(GND) U94.1(GND) U95.3(GND) U95.8(GND) U99.8(GND) U99.15(~{OE}) U101.8(GND) U102.4(GND) U103.4(GND) U104.2(GND) X1.2(GND) ; also on sheet 1 2 3 4 5 6 8 19 20 21 22 23 24 25 26 27 28 29 30 31 32 33 34 35
GNDPROFI: C323.2(NEG) C325.2(NEG) C430.2 C431.2 C433.2 C434.2 J14.5 L2.6 L2.7 R573.1(P1) R578.1(P1) U52.3(GND) U52.4(~{EN}) U74.9(GND2) U74.11(GND2) U74.14(GND2) U74.15(GND2) U80.2 U81.2
GNDUSB1: C557.2 C558.2 J23.S1 J23.S2 R812.1(P1)
GNDUSB2: C559.2 C560.2 J45.S1 J45.S2 J45.S3 J45.S4 R813.1(P1)
V3_3D: C88.1 C119.1 C120.1 C122.1 C127.1 C209.1 C210.1 C220.1 C221.1 C319.1 C432.1 C435.1 C532.1 L2.2 L2.3 R56.2(P2) R67.2(P2) R120.2(P2) R121.2(P2) R122.2(P2) R131.2(P2) R134.2(P2) R141.1(P1) R143.1(P1) R144.1(P1) R145.1(P1) R146.1(P1) R149.2 R152.2(P2) R153.2 R259.2 R366.2 R383.2(P2) R384.2(P2) R421.2 R422.2(P2) R423.2(P2) R434.2(P2) R435.2(P2) R436.2(P2) R437.2(P2) R438.2(P2) R439.2(P2) R440.2(P2) R441.2(P2) R442.2(P2) R443.2(P2) R444.2(P2) R445.2(P2) R446.2(P2) R447.2(P2) R448.2(P2) R449.2(P2) R450.2(P2) R551.2 R730.2(P2) R731.2(P2) R782.2(P2) R783.2(P2) R790.2 R800.2 R808.2 R902.2 R938.2 R939.2 R941.2 R943.2 R945.2 R948.2 R956.2(P2) U8.10(VIN) U13.21(VDD33_IO) U19.5(VCC) U33.8(VCC) U69.5(VCC) U73.1(VCC) U74.4(VCC1) U78.5(VCC) U92.10(VIN) U99.16(VCC) U101.15(2~{G}) U101.16(VCC) U102.8(VCC) U103.8(VCC) X1.4(VCC) ; also on sheet 2 3 4 5 6 8 19 21 22 23 24 25 26 27 28 29 30 31 32 33 34 35
V3_3D_PROFIA: L2.4 U74.1(D1)
V3_3D_PROFIB: L2.1 U74.2(D2)
V3_3D_PRU1ETH1JCK: C116.1 C117.1 J5.3 J5.4 R121.1(P1)
V5_0D: C208.1 J37.27 J37.28 R386.1(P1) R388.1(P1) R389.1(P1) R390.1(P1) R391.1(P1) R392.1(P1) R395.1(P1) R396.1(P1) U66.2(IN) U66.3(IN) U94.2(IN) U94.3(IN) ; also on sheet 4 21 34
V5_0VOP: C195.1 C205.1 C207.1 U28.5(VCC) U72.15(5VOP)
V12_0D: C196.1 J37.2 J37.4 J37.6 J37.8 J37.10 J37.12 J37.14 J37.16 R379.1 ; also on sheet 21 23
VDDR2_VREF: C531.1 U92.6(REFOUT) ; also on sheet 20
VDDR2_VTT: C525.1 C526.1 C527.1 C528.1 C530.1 C534.1 C535.1 C536.1 C537.1 C538.1 C539.1 R756.1(P1) R757.1(P1) R758.1(P1) R759.1(P1) R760.1(P1) R761.1(P1) R762.1(P1) R763.1(P1) R764.1(P1) R765.1(P1) R766.1(P1) R767.1(P1) R768.1(P1) R769.1(P1) R770.1(P1) R771.1(P1) R772.1(P1) R773.1(P1) R774.1(P1) R775.1(P1) R776.1(P1) R777.1(P1) R778.1(P1) R779.1(P1) R784.2(P2) R807.1(P1) U92.3(VO)
VDDR_VREF: C99.1 U8.6(REFOUT) ; also on sheet 1
VDDR_VTT: C87.1 C89.1 C93.1 C94.1 C95.1 C96.1 C97.1 C98.1 C100.1 C313.1 C314.1 R49.1(P1) R50.1(P1) R51.1(P1) R52.1(P1) R53.1(P1) R54.1(P1) R55.1(P1) R57.1(P1) R58.1(P1) R59.1(P1) R60.1(P1) R61.1(P1) R62.1(P1) R63.1(P1) R64.1(P1) R65.1(P1) R66.1(P1) R68.1(P1) R69.2(P2) R70.1(P1) R71.1(P1) R72.1(P1) R73.1(P1) R74.1(P1) R75.1(P1) R806.1(P1) U8.3(VO)
VDDS_DDR: C84.1 C85.2 C87.2 C89.2 C90.1 C91.1 C92.1 C314.2 C526.2 C529.2 C538.2 C539.2 C540.1 C541.1 C542.1 C543.1 R45.2 R786.2 U8.2(VLDOIN) U92.2(VLDOIN) ; also on sheet 1 20 21 22
AM57XX_CLKOUT3: R300.2(P2) R905.2(P2) R967.2 U1.C23(XREF_CLK3/CLKOUT3)
AM57XX_GPIO_IND_LDn: R371.2(P2) R800.1 U1.AF4(VIN1A_D15/GPIO)
AM57XX_GPMC_AD0: R434.1(P1) R453.2 ; also on sheet 34
AM57XX_GPMC_AD1: R435.1(P1) R454.2 ; also on sheet 34
AM57XX_GPMC_AD2: R436.1(P1) R455.2 ; also on sheet 34
AM57XX_GPMC_AD3: R437.1(P1) R456.2 ; also on sheet 34
AM57XX_GPMC_AD4: R438.1(P1) R457.2 ; also on sheet 34
AM57XX_GPMC_AD5: R439.1(P1) R458.2 ; also on sheet 34
AM57XX_GPMC_AD6: R440.1(P1) R459.2 ; also on sheet 34
AM57XX_GPMC_AD7: R441.1(P1) R460.2 ; also on sheet 34
AM57XX_GPMC_AD8: R442.1(P1) R461.2 ; also on sheet 34
AM57XX_GPMC_AD9: R443.1(P1) R462.2 ; also on sheet 34
AM57XX_GPMC_AD10: R444.1(P1) R463.2 ; also on sheet 34
AM57XX_GPMC_AD11: R445.1(P1) R464.2 ; also on sheet 34
AM57XX_GPMC_AD12: R446.1(P1) R465.2 ; also on sheet 34
AM57XX_GPMC_AD13: R447.1(P1) R466.2 ; also on sheet 34
AM57XX_GPMC_AD14: R448.1(P1) R467.2 ; also on sheet 34
AM57XX_GPMC_AD15: R449.1(P1) R468.2 ; also on sheet 34
AM57XX_I2C1_SCL: R384.1(P1) R385.2(P2) R393.2(P2) U1.C20(I2C1_SCL)
AM57XX_I2C1_SDA: R383.1(P1) R387.2(P2) R394.2(P2) U1.C21(I2C1_SDA)
AM57XX_INDETHER_LED0_RED: R976.1 ; also on sheet 34
AM57XX_INDETHER_LED0_YEL: R965.2 ; also on sheet 34 35
AM57XX_INDETHER_LED1_RED: R966.2 ; also on sheet 34 35
AM57XX_INDETHER_LED1_YEL: R968.1 ; also on sheet 34
AM57XX_PR1_UART0_RXD: R575.2(P2) U1.F2(VIN2A_D0/PR1_UART0_RXD) ; also on sheet 34
AM57XX_PR1_UART0_TXD: R574.2(P2) U1.F3(VIN2A_D1/PR1_UART0_TXD) ; also on sheet 27 34
AM57XX_PR2_PROFI_TXEN: U1.U3(RMII50MHZCLK/PR2_GPIO) ; also on sheet 34
AM57XX_PRU1ETH1_MRCLK: R129.2(P2) ; also on sheet 25
AM57XX_PRU1ETH1_TXCLK: R123.2(P2) U1.C1(VIN2A_D6/PR1_MII_MT1_CLK) ; also on sheet 34
AM57XX_PRU1ETH1_TXD0: R125.2(P2) ; also on sheet 25
AM57XX_PRU1ETH1_TXD1: R126.2(P2) ; also on sheet 25
AM57XX_PRU1ETH1_TXD2: R127.2(P2) U1.E6(VIN2A_D9/PR1_MII1_TXD2)
AM57XX_PRU1ETH1_TXD3: R128.2(P2) U1.F5(VIN2A_D8/PR1_MII1_TXD3) ; also on sheet 34
AM57XX_PRU1ETH1_TXEN: R124.2(P2) U1.E4(VIN2A_D7/PR1_MII1_TXEN)
AM57XX_PRU1ETH_MDCLK: R140.2(P2) U1.D3(VIN2A_D10/PR1_MDIO_MDCLK) ; also on sheet 24 34
AM57XX_PRU1ETH_MDDATA: R142.2(P2) U1.F6(VIN2A_D11/PR1_MDIO_DATA) ; also on sheet 24
AM57XX_RGMII1_RD0: R139.2(P2) ; also on sheet 25
AM57XX_RGMII1_RD1: R148.2(P2) ; also on sheet 25
AM57XX_RGMII1_RD2: R150.2(P2) ; also on sheet 25
AM57XX_RGMII1_RD3: R132.2(P2) ; also on sheet 25
AM57XX_RGMII1_RXCLK: R135.2(P2) ; also on sheet 25
AM57XX_RGMII1_RXCTL: R133.2(P2) ; also on sheet 25
AM57XX_RGMII1_TD0: R136.2(P2) ; also on sheet 25
AM57XX_RGMII1_TD1: R137.2(P2) ; also on sheet 25
AM57XX_RGMII1_TD2: R130.2(P2) ; also on sheet 25
AM57XX_RTCK: R426.2 U1.E18(RTCK)
AM57XX_SPI1_CS0: R369.2(P2) U1.D17(MCASP4_AXR1/SPI3_CS0)
AM57XX_SPI1_D1: R377.2(P2) U1.A21(MCASP4_FSX/SPI3_D1)
AM57XX_SPI1_SCLK: R367.2(P2) U1.C18(MCASP4_ACLKX/SPI3_SCLK)
AM57XX_VOUT1_D2: R711.2(P2) ; also on sheet 5
AM57XX_VOUT1_D3: R714.2(P2) ; also on sheet 5
AM57XX_VOUT1_D4: R715.2(P2) ; also on sheet 5
AM57XX_VOUT1_D5: R716.2(P2) ; also on sheet 5
AM57XX_VOUT1_D6: R717.2(P2) ; also on sheet 5
AM57XX_VOUT1_D7: R718.2(P2) ; also on sheet 5
AM57XX_VOUT1_D10: R712.2(P2) ; also on sheet 5
AM57XX_VOUT1_D11: R719.2(P2) ; also on sheet 5
AM57XX_VOUT1_D12: R720.2(P2) ; also on sheet 5
AM57XX_VOUT1_D13: R721.2(P2) ; also on sheet 5
AM57XX_VOUT1_D14: R722.2(P2) ; also on sheet 5
AM57XX_VOUT1_D15: R723.2(P2) ; also on sheet 5
AM57XX_VOUT1_D18: R713.2(P2) ; also on sheet 5
AM57XX_VOUT1_D19: R724.2(P2) ; also on sheet 5
AM57XX_VOUT1_D20: R725.2(P2) ; also on sheet 5
AM57XX_VOUT1_D21: R726.2(P2) ; also on sheet 5
AM57XX_VOUT1_D22: R727.2(P2) ; also on sheet 5
AM57XX_VOUT1_D23: R728.2(P2) ; also on sheet 5
AM574X_USB1_3_0_STDA_SSTX+: C555.1 U1.AD11(USB_TXP0)
AM574X_USB1_3_0_STDA_SSTX-: C554.1 U1.AC11(USB_TXN0)
AM574X_USB1_DM: L11.1 U1.AC12(USB1_DM)
AM574X_USB1_DP: L11.2 U1.AD12(USB1_DP)
AM574X_USB1_DRVVBUS: R557.2(P2) R979.1 U1.AB10(USB1_DRVVBUS)
AM574X_USB2_DM: L33.2 U1.AF11(USB2_DM)
AM574X_USB2_DP: L33.1 U1.AE11(USB2_DP)
AM574X_USB2_DRVVBUS: R787.2(P2) R972.1 U1.AC10(USB2_DRVVBUS)
AM574X_VIN4B_DATA0: R260.2(P2) U1.R6(GPMC_A0/VIN4B_D0)
AM574X_VIN4B_DATA1: R261.2(P2) U1.T9(GPMC_A1/VIN4B_D1)
AM574X_VIN4B_DATA2: R263.2(P2) U1.T6(GPMC_A2/VIN4B_D2)
AM574X_VIN4B_DATA3: R267.2(P2) U1.T7(GPMC_A3/VIN4B_D3)
AM574X_VIN4B_DATA4: R269.2(P2) U1.P6(GPMC_A4/VIN4B_D4)
AM574X_VIN4B_DATA5: R271.2(P2) U1.R9(GPMC_A5/VIN4B_D5)
AM574X_VIN4B_DATA6: R262.1(P1) U1.R5(GPMC_A6/VIN4B_D6)
AM574X_VIN4B_DATA7: R264.1(P1) U1.P5(GPMC_A7/VIN4B_D7)
AM574X_VIN4B_DE: R273.2(P2) U1.P9(GPMC_A11/VIN4B_DE1)
AM574X_VIN4B_FLD: R274.1(P1) U1.P4(GPMC_A12/VIN4B_FLD1)
AM574X_VIN4B_HSYNC: R258.1(P1) U1.N7(GPMC_A8/VIN4B_HSYNC1)
AM574X_VIN4B_PCLK: R265.2(P2) U1.N9(GPMC_A10/VIN4B_CLK1)
AM574X_VIN4B_VSYNC: R257.1(P1) U1.R4(GPMC_A9/VIN4B_VSYNC1)
BUFFER_OE_S20: R945.1 R961.2 U103.7(2~{OE})
BUFFER_OE_T16: R939.1 R959.2 U102.1(1~{OE})
BUFFER_OE_T16_2: R941.1 R974.1 U102.7(2~{OE})
CAM1_DATA0: J9.3 R260.1(P1)
CAM1_DATA1: J9.5 R261.1(P1)
CAM1_DATA2: J9.7 R263.1(P1)
CAM1_DATA3: J9.13 R267.1(P1)
CAM1_DATA4: J9.15 R269.1(P1)
CAM1_DATA5: J9.17 R271.1(P1)
CAM1_DATA6: J9.6 R262.2(P2)
CAM1_DATA7: J9.8 R264.2(P2)
CAM1_FIELD: J9.20 R274.2(P2)
CAM1_GIO0: J9.16 R259.1
CAM1_HSYNC: J9.4 R258.2(P2)
CAM1_PCLK: J9.9 R265.1(P1)
CAM1_VSYNC: J9.2 R257.2(P2)
CAM1_WEN: J9.19 R273.1(P1)
CAM_ENn: J9.18 ; also on sheet 34
DDR2_A0: R761.2(P2) ; also on sheet 20
DDR2_A1: R763.2(P2) ; also on sheet 20
DDR2_A2: R762.2(P2) ; also on sheet 20
DDR2_A3: R765.2(P2) ; also on sheet 20
DDR2_A4: R764.2(P2) ; also on sheet 20
DDR2_A5: R766.2(P2) ; also on sheet 20
DDR2_A6: R768.2(P2) ; also on sheet 20
DDR2_A7: R767.2(P2) ; also on sheet 20
DDR2_A8: R770.2(P2) ; also on sheet 20
DDR2_A9: R769.2(P2) ; also on sheet 20
DDR2_A10: R771.2(P2) ; also on sheet 20
DDR2_A11: R773.2(P2) ; also on sheet 20
DDR2_A12: R772.2(P2) ; also on sheet 20
DDR2_A13: R775.2(P2) ; also on sheet 20
DDR2_A14: R774.2(P2) ; also on sheet 20
DDR2_A15: R807.2(P2) ; also on sheet 20
DDR2_BA0: R777.2(P2) ; also on sheet 20
DDR2_BA1: R776.2(P2) ; also on sheet 20
DDR2_BA2: R779.2(P2) ; also on sheet 20
DDR2_CASn: R759.2(P2) ; also on sheet 20
DDR2_CKE: R756.2(P2) ; also on sheet 20
DDR2_CLK: R780.2(P2) ; also on sheet 20
DDR2_CLKn: R781.2(P2) ; also on sheet 20
DDR2_CS0n: R757.2(P2) ; also on sheet 20
DDR2_ODT: R778.2(P2) ; also on sheet 20
DDR2_RASn: R758.2(P2) ; also on sheet 20
DDR2_RESETn: R913.2 ; also on sheet 20
DDR2_WEn: R760.2(P2) ; also on sheet 20
DDR_A0: R54.2(P2) ; also on sheet 1
DDR_A1: R57.2(P2) ; also on sheet 1
DDR_A2: R55.2(P2) ; also on sheet 1
DDR_A3: R58.2(P2) ; also on sheet 1
DDR_A4: R59.2(P2) ; also on sheet 1
DDR_A5: R60.2(P2) ; also on sheet 1
DDR_A6: R61.2(P2) ; also on sheet 1
DDR_A7: R62.2(P2) ; also on sheet 1
DDR_A8: R63.2(P2) ; also on sheet 1
DDR_A9: R64.2(P2) ; also on sheet 1
DDR_A10: R66.2(P2) ; also on sheet 1
DDR_A11: R65.2(P2) ; also on sheet 1
DDR_A12: R68.2(P2) ; also on sheet 1
DDR_A13: R70.2(P2) ; also on sheet 1
DDR_A14: R71.2(P2) ; also on sheet 1
DDR_A15: R806.2(P2) ; also on sheet 1
DDR_BA0: R72.2(P2) ; also on sheet 1
DDR_BA1: R73.2(P2) ; also on sheet 1
DDR_BA2: R74.2(P2) ; also on sheet 1
DDR_CASn: R52.2(P2) ; also on sheet 1
DDR_CKE: R49.2(P2) ; also on sheet 1
DDR_CLK: R46.2(P2) ; also on sheet 1
DDR_CLKn: R47.2(P2) ; also on sheet 1
DDR_CS0n: R50.2(P2) ; also on sheet 1
DDR_ODT: R75.2(P2) ; also on sheet 1
DDR_RASn: R51.2(P2) ; also on sheet 1
DDR_RESETn: R912.2 ; also on sheet 1
DDR_WEn: R53.2(P2) ; also on sheet 1
DECODER_1A: R965.1 U101.2(1A)
DECODER_1B: R966.1 U101.3(1B)
DECODER_1G: R938.1 R970.1 U101.1(1~{G})
DRAIN0: D5.1(Cathode) J37.19 U73.3(DRAIN0)
DRAIN1: D6.1(Cathode) J37.20 U73.4(DRAIN1)
DRAIN2: D7.1(Cathode) J37.21 U73.5(DRAIN2)
DRAIN3: D8.1(Cathode) J37.22 U73.6(DRAIN3)
DRAIN4: D9.1(Cathode) J37.23 U73.11(DRAIN4)
DRAIN5: D10.1(Cathode) J37.24 U73.12(DRAIN5)
DRAIN6: D11.1(Cathode) J37.25 U73.13(DRAIN6)
DRAIN7: D12.1(Cathode) J37.26 U73.14(DRAIN7)
EMU2: J18.13(TR_CLK0) R711.1(P1)
EMU3: J18.17(TRD0.0) R712.1(P1)
EMU4: J18.23(TRD0.3) R713.1(P1)
EMU5: J18.25(TRD0.4) R714.1(P1)
EMU6: J18.27(TRD0.5) R715.1(P1)
EMU7: J18.29(TRD0.6) R716.1(P1)
EMU8: J18.31(TRD0.7) R717.1(P1)
EMU9: J18.33(TRD0.8) R718.1(P1)
EMU10: J18.35(TRD0.9) R719.1(P1)
EMU11: J18.37(TRD3.0) R720.1(P1)
EMU12: J18.39(TRD3.1) R721.1(P1)
EMU13: J18.41(TRD3.2) R722.1(P1)
EMU14: J18.43(TRD3.3) R723.1(P1)
EMU15: J18.45(TRD3.4) R724.1(P1)
EMU16: J18.47(TRD3.5) R725.1(P1)
EMU17: J18.49(TRD3.6) R726.1(P1)
EMU18: J18.51(TRD3.7) R727.1(P1)
EMU19: J18.53(TRD3.8) R728.1(P1)
EMU_RSTn: C223.1 J18.6(RESETn) R429.2(P2) R450.1(P1)
GPIO_AM574X_USB2_ID: R788.2(P2) U1.AF2(VIN1A_D12/GPIO)
GPIO_PRU1_ETH1_RESETn: R154.2(P2) ; also on sheet 34
HDQ: R300.1(P1) ; also on sheet 34
IND_I2C_SCL: R275.1(P1) R393.1(P1) U33.6(SCL) ; also on sheet 5 19 23 28 34
IND_I2C_SDA: R277.1(P1) R394.1(P1) U33.5(SDA) ; also on sheet 5 19 23 28 34
INDETHER_LED0_RED: R975.1 ; also on sheet 35
INDETHER_LED1_YEL: R969.1 ; also on sheet 35
INDUS_INPUT0: J37.1 R368.2
INDUS_INPUT1: J37.3 R370.2
INDUS_INPUT2: J37.5 R372.2
INDUS_INPUT3: J37.7 R374.2
INDUS_INPUT4: J37.9 R373.2
INDUS_INPUT5: J37.11 R375.2
INDUS_INPUT6: J37.13 R376.2
INDUS_INPUT7: J37.15 R378.2
INDUS_INPUTCLK: R367.1(P1) U72.25(CLK)
INDUS_INPUTCSn: R369.1(P1) U72.24(~{CE})
INDUS_INPUTLDn: R371.1(P1) U72.26(~{LD})
INDUS_INPUTSO: U28.2(A) U72.23(SOP)
JTAG_EMU0: J18.19(TRD0.1) R422.1(P1) U1.G21(EMU0) ; also on sheet 2
JTAG_EMU1: J18.21(TRD0.2) R423.1(P1) U1.D24(EMU1) ; also on sheet 2
JTAG_TCK: R3.2 U1.E20(TCK) ; also on sheet 2
JTAG_TDI: J18.5(TDI) U1.D23(TDI) ; also on sheet 2
JTAG_TDO: J18.4(TDO) U1.F19(TDO) ; also on sheet 2
JTAG_TMS: J18.2(TMS) U1.F18(TMS) ; also on sheet 2
JTAG_TRSTn: J18.8(TRSTPD) R433.2(P2) U1.D20(TRSTn) ; also on sheet 2
JTAGPOD_PRES: U19.4(Y) ; also on sheet 2
PHY_RESETn: U69.2(B) ; also on sheet 24 25 26 27 28 31
PMIC_RESET_IN: R981.1 U104.1(~{RESET}) ; also on sheet 19
PR2_EDC_SYNC0: U103.5(2A) ; also on sheet 5 34
PR2_UART0_RXD: R942.1 R947.2 ; also on sheet 5 34
PR2_UART0_TXD: R940.1 ; also on sheet 5 34
PROFIBUS_A: J14.3 R577.1(P1) U74.12(A) U81.1
PROFIBUS_B: J14.8 R578.2(P2) U74.13(B) U80.1
PRU1ETH1_25MHzCLK: U13.23(XI) ; also on sheet 28
PRU1ETH1_COL: R148.1(P1) R150.1(P1) R151.2(P2) R152.1(P1) R956.1(P1) U13.29(COL)
PRU1ETH1_CRS: R139.1(P1) U13.27(CRS)
PRU1ETH1_INTn: U13.8(PWRDNn/INTn) ; also on sheet 34
PRU1ETH1_LINKLED: R131.1(P1) R138.2(P2) U13.17(LED_LINK)
PRU1ETH1_MDC: R140.1(P1) U13.20(MDC)
PRU1ETH1_MDIO: R120.1(P1) R142.1(P1) U13.19(MDIO)
PRU1ETH1_RESETn: U13.18(RESET_N) U69.4(Y)
PRU1ETH1_RXCLK: R129.1(P1) U13.25(RX_CLK) ; also on sheet 34
PRU1ETH1_RXD0: R133.1(P1) R158.2(P2) U13.30(RXD_0)
PRU1ETH1_RXD1: R135.1(P1) R157.2(P2) U13.31(RXD_1) ; also on sheet 34
PRU1ETH1_RXD2: R136.1(P1) R156.2(P2) U13.32(RXD_2)
PRU1ETH1_RXD3: R137.1(P1) R155.2(P2) U13.1(RXD_3) ; also on sheet 34
PRU1ETH1_RXDV: R130.1(P1) U13.26(RX_DV)
PRU1ETH1_RXERR: R132.1(P1) U13.28(RX_ERR) ; also on sheet 34
PRU1ETH1_TXCLK: R123.1(P1) U13.2(TX_CLK)
PRU1ETH1_TXD0: R125.1(P1) U13.4(TXD_0)
PRU1ETH1_TXD1: R126.1(P1) U13.5(TXD_1) ; also on sheet 34
PRU1ETH1_TXD2: R127.1(P1) U13.6(TXD_2)
PRU1ETH1_TXD3: R128.1(P1) U13.7(TXD_3)
PRU1ETH1_TXEN: R124.1(P1) U13.3(TX_EN)
PRU1ETHER1_RDN: J5.6 R143.2(P2) U13.9(RD-)
PRU1ETHER1_RDP: J5.5 R144.2(P2) U13.10(RD+)
PRU1ETHER1_TDN: J5.2 R145.2(P2) U13.11(TD-)
PRU1ETHER1_TDP: J5.1 R146.2(P2) U13.12(TD+)
PTP_PPS_OE: J51.1 R948.1 R973.1
RTCK: J18.7(RTCK) R426.1
SRCCLK: R276.1 ; also on sheet 5
SYS_WARMRESETn: U78.4(Y) ; also on sheet 2 31
TCK: J18.3(TCK) R3.1
TIMER15: R935.1 ; also on sheet 34
TIMER16: R967.1 U102.2(1A)
TIMER16_2: R977.1 U102.5(2A)
USB1_3_0_STDA_SSRX+: J23.6(STDA_SSRX+) U1.AE12(USB_RXP0) U95.2(D1-)
USB1_3_0_STDA_SSRX-: J23.5(STDA_SSRX-) U1.AF12(USB_RXN0) U95.1(D1+)
USB1_3_0_STDA_SSTX+: C555.2 J23.9(STDA_SSTX+) U95.5(D2-)
USB1_3_0_STDA_SSTX-: C554.2 J23.8(STDA_SSTX-) U95.4(D2+)
USB1_CONN_DM: J23.2(DM) L11.4 U64.2(D-)
USB1_CONN_DP: J23.3(DP) L11.3 U64.1(D+)
USB1_OVRCURn: R551.1 U66.5(~{OC})
USB1_VBUS_EN: R553.1 R557.1(P1) R978.1 U66.4(EN)
USB2_CONN_DM: J45.2(DM) L33.3 U93.2(D-)
USB2_CONN_DP: J45.3(DP) L33.4 U93.1(D+)
USB2_ID: J45.4(ID) R788.1(P1) R808.1 U93.3(ID)
USB2_OVRCURn: R790.1 U94.5(~{OC})
USB2_VBUS_EN: R787.1(P1) R791.1 R971.1 U94.4(EN)
VADD33_PRU1ETH1: C118.1 R141.2(P2) U13.14(AVDD33)
VMAIN: C152.1 C579.1 J9.1 R982.1(P1) U104.6(VDD) ; also on sheet 5 19 21 34
VPROFI: C323.1(POS) C325.1(POS) C430.1 C431.1 J14.6 R577.2(P2) U52.7(OUT) U52.8(OUT) U74.16(VCC2)
VPROFI_SRC: C433.1 C434.1 D14.1(k) D15.1(k) U52.5(IN) U52.6(IN)
VPROFI_TRANSA: D15.2(A) L2.8
VPROFI_TRANSB: D14.2(A) L2.5
VPWRIN_JCK: U104.5(SENSE) ; also on sheet 19
VRTC_OUT: R981.2 ; also on sheet 19 22 29
VUSB_VBUS1: C311.1 J23.1(VBUS) U66.6(OUT) U66.7(OUT) U66.8(OUT)
VUSB_VBUS2: C546.1 C547.1 J45.1(VBUS) J50.2 U93.6(VBUS) U94.6(OUT) U94.7(OUT) U94.8(OUT) ; also on sheet 19
N11217419: C85.1 R46.1(P1) R47.1(P1)
N11219802: R67.1(P1) U8.7(EN)
N11219922: R56.1(P1) U8.9(PGOOD)
N11219986: C101.1 R69.1(P1) U8.5(VOSNS)
N11220684: C86.1 R45.1 R48.2 U8.1(REFIN)
N12225140: J5.11 R122.1(P1)
N12225158: C123.1 C124.1 C125.1 C126.1 U13.13(PFBIN1) U13.15(PFBOUT) U13.24(PFBIN2)
N12225278: J5.10 R151.1(P1)
N12226470: J5.9 R134.1(P1)
N12226568: R153.1 R154.1(P1) U69.1(A)
N15911835: R147.2(P2) U13.16(RBIAS)
N16251668: R385.1(P1) U73.15(SCL)
N16251678: R387.1(P1) U73.2(SDA)
N16700927: J5.12 R138.1(P1)
N16839102: C206.1 R379.2 U72.14(VCC)
N16839202: R382.2(P2) U72.13(RLIM)
N16839209: R381.2(P2) U72.2(DB1)
N16839216: R380.2(P2) U72.1(DB0)
N16844891: D6.2(Anode) R388.2(P2)
N16844892: D11.2(Anode) R395.2(P2)
N16844893: D12.2(Anode) R396.2(P2)
N16844894: D9.2(Anode) R391.2(P2)
N16844899: D10.2(Anode) R392.2(P2)
N16844909: D5.2(Anode) R386.2(P2)
N16844924: D8.2(Anode) R390.2(P2)
N16844930: D7.2(Anode) R389.2(P2)
N17007255: R366.1 R377.1(P1) U28.4(Y)
N17745676: J9.22 R275.2(P2)
N17745678: J9.24 R277.2(P2)
N17745710: J9.23 R903.1
N19290398: R421.1 U33.7(WP)
N19634423: R579.2(P2) U74.6(~{RE})
N19634430: R574.1(P1) U74.8(D)
N19634431: R575.1(P1) U74.5(R)
N19634433: R576.1(P1) U74.7(DE)
N19700674: J18.1(VREF_DBG) R730.1(P1)
N19700725: J18.12(VREF_TR) R731.1(P1)
N19707292: J18.15(TGT_DETECT) R587.1(P1)
N19708748: R429.1(P1) U78.2(A)
N20962931: C421.1 J18.58(GND) R149.1 U19.2(A)
N21552786: C544.1 R785.2 R786.1 U92.1(REFIN)
N21553219: C529.1 R780.1(P1) R781.1(P1)
N21553307: R783.1(P1) U92.7(EN)
N21553371: R782.1(P1) U92.9(PGOOD)
N21553379: C533.1 R784.1(P1) U92.5(VOSNS)
N21605448: C545.1 J50.1
N21620210: C197.1 R368.1 U72.3(IP0)
N21620213: C198.1 R370.1 U72.5(IP1)
N21620216: C199.1 R372.1 U72.7(IP2)
N21620219: C200.1 R374.1 U72.9(IP3)
N21620222: C201.1 R373.1 U72.11(IP4)
N21620225: C202.1 R375.1 U72.18(IP5)
N21620228: C203.1 R376.1 U72.20(IP6)
N21620231: C204.1 R378.1 U72.22(IP7)
N22642197: R276.2 R903.2 R905.1(P1) X1.3(OUT)
N22691021: R576.2(P2) U1.F4(VIN2A_D5/PR1_PRU1_R30_2)
N24440306: R902.1 X1.1(EN)
N24733277: R974.2 U99.14(4B1)
N24733350: R975.2 U99.13(4B2)
N24733388: R976.2 U99.12(4A)
N24733458: R977.2 U99.11(3B1)
N24733465: R978.2 U99.10(3B2)
N24733472: R979.2 U99.9(3A)
N24733813: R935.2 U99.5(2B1)
N24736796: R940.2 U102.3(2Y)
N24737086: R942.2 U102.6(1Y)
N24737397: R943.1 R980.1 U103.1(1~{OE})
N24737443: R947.1 U103.3(2Y)
N24737493: R946.2 U103.6(1Y)
N25402841: R959.1 U101.4(1Y0)
N25402875: R960.1 U101.5(1Y1)
N25402909: R961.1 U101.6(1Y2)
N25403534: R964.1 U103.2(1A)
N25403747: R968.2 U99.4(1A)
N25403773: R969.2 U99.3(1B2)
N25403799: R970.2 U99.2(1B1)
N25403922: R971.2 U99.6(2B2)
N25403942: R972.2 U99.7(2A)
N25404009: R973.2 U99.1(S)
N25485278: C580.1 R982.2(P2) U104.4(CT)
N25485584: TP25.1 U104.3(~{MR})

Not connected (* = marked no-connect by the designer): J5 7*; J9 10* 14*; J14 1* 2* 4* 7* 9*; J18 9(TRSTn)* 10(EXTE)* 11(EXTF)* 14(TR_CLK1)* 18(TRD1.0)* 20(TRD1.1)* 22(TRD1.2)* 24(TRD1.3)* 26(TRD1.4)* 28(TRD1.5)* 30(TRD1.6)* 32(TRD1.7)* 34(TRD1.8)* 36(TRD1.9)* 38(TRD2.0)* 40(TRD2.1)* 42(TRD2.2)* 44(TRD2.3)* 46(TRD2.4)* 48(TRD2.5)* 50(TRD2.6)* 52(TRD2.7)* 54(TRD2.8)* 55(TRD3.9)* 56(TRD2.9)* 59(TR_CLK3)* 60(TR_CLK2)*; J37 18*; R946 1*; R960 2*; R964 2*; R980 2*; U13 22(XO)*; U19 1(NC)*; U28 1(NC)*; U52 1(NC/FB)* 2(PG)*; U72 4(RE0)* 6(RE1)* 8(RE2)* 10(RE3)* 12(RE4)* 16(TOK)* 17(RE5)* 19(RE6)* 21(RE7)* 27(SIP)*; U74 10(ISODE)*; U78 1(NC)*; U93 5(NC)*; U95 6(NC6)* 7(NC7)* 9(NC9)* 10(NC10)*; U101 7(1Y3)* 9(2Y3)* 10(2Y2)* 11(2Y1)* 12(2Y0)* 13(2B)* 14(2A)*

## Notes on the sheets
sheet 10
- AM572x Industrial Development Kit
sheet 14
- USB1 Port
sheet 15
- ID Memory
- JTAG Connector
- Boot Configuration
sheet 16
- USB2 Port
sheet 17
- Note: MDIO Address = 0x01
sheet 18
- Industrial INPUTS
- Digital OUTPUTS
- I/O Expansion Header
